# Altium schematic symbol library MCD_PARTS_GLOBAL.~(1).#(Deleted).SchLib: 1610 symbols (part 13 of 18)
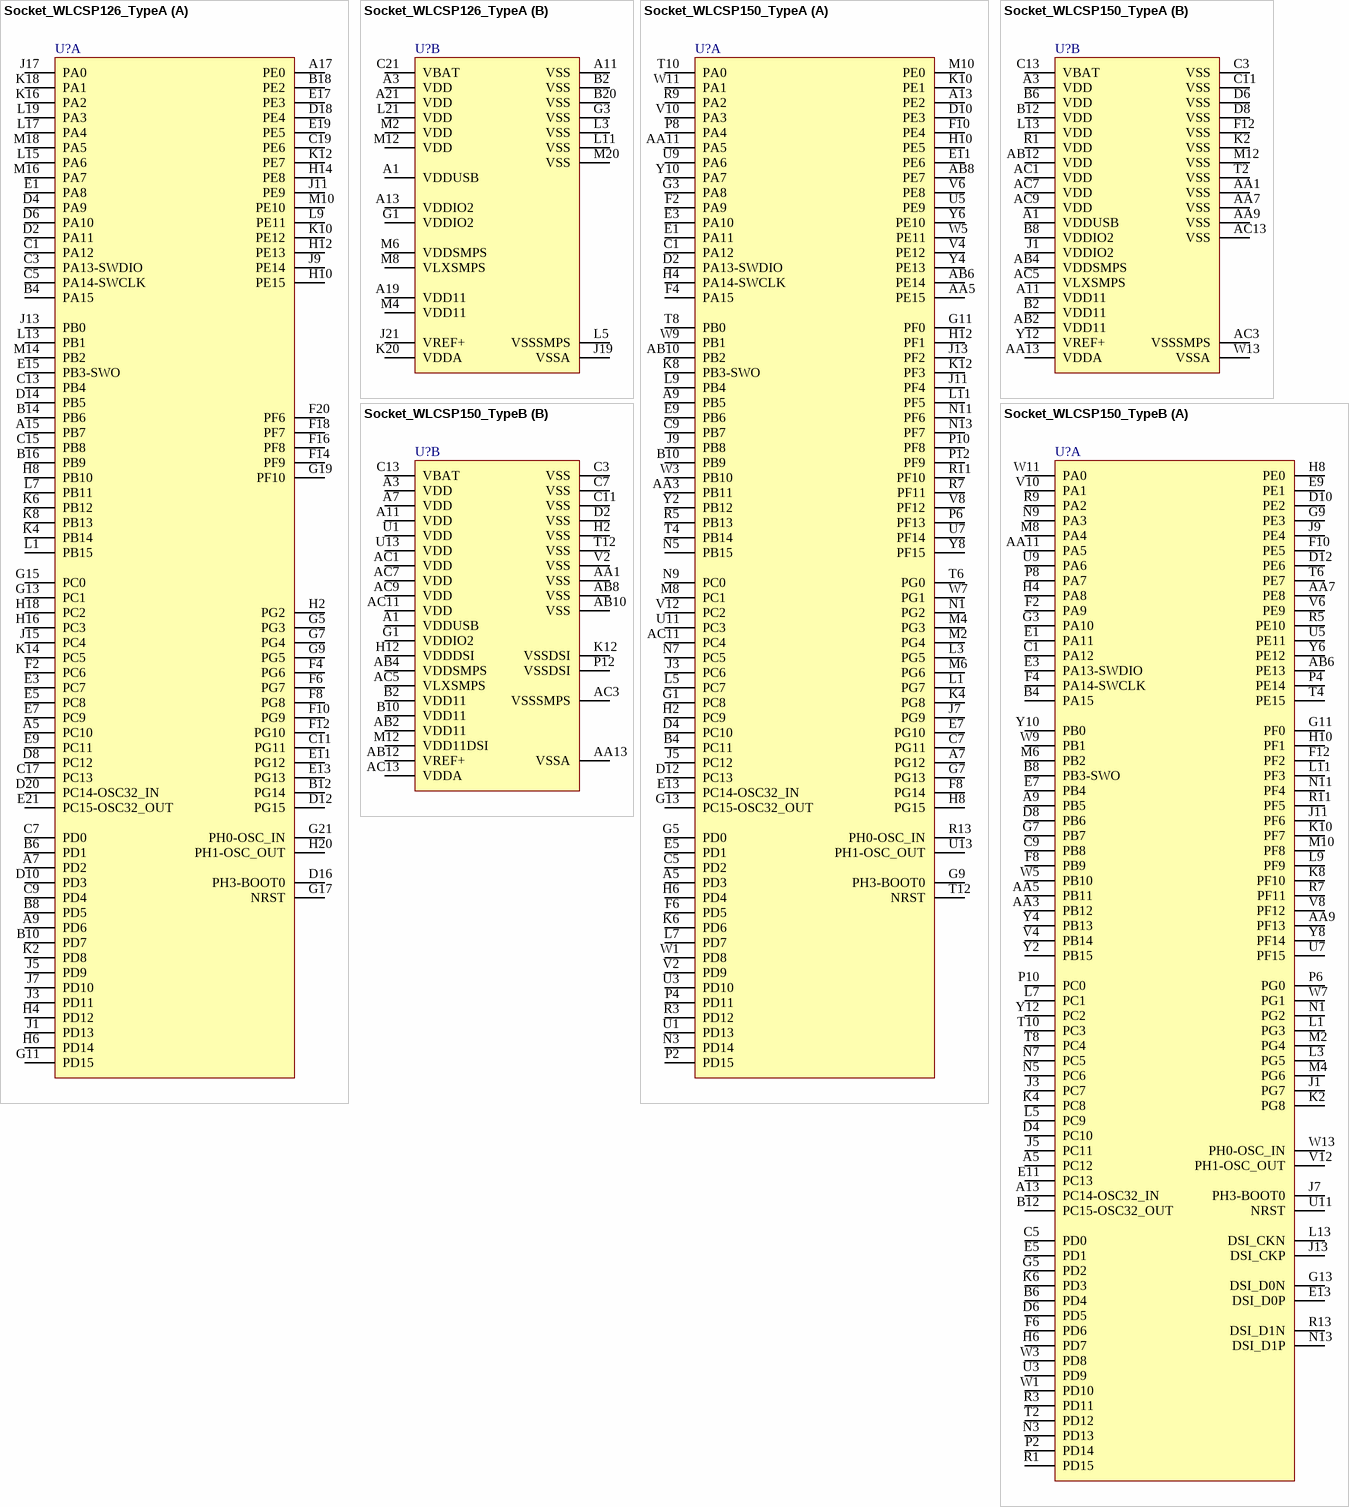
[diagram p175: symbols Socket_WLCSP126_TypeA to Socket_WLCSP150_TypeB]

## Socket_WLCSP126_TypeA
designator U?
part A pins: A5 PC10, A7 PD2, A9 PD6, A15 PB7, A17 PE0, B4 PA15, B6 PD1, B8 PD5, B10 PD7, B12 PG14, B14 PB6, B16 PB9, B18 PE2, C1 PA12, C3 PA13-SWDIO, C5 PA14-SWCLK, C7 PD0, C9 PD4, C11 PG11, C13 PB4, C15 PB8, C17 PC13, C19 PE6, D2 PA11, D4 PA9, D6 PA10, D8 PC12, D10 PD3, D12 PG15, D14 PB5, D16 PH3-BOOT0, D18 PE4, D20 PC14-OSC32_IN, E1 PA8, E3 PC7, E5 PC8, E7 PC9, E9 PC11, E11 PG12, E13 PG13, E15 PB3-SWO, E17 PE3, E19 PE5, E21 PC15-OSC32_OUT, F2 PC6, F4 PG6, F6 PG7, F8 PG8, F10 PG9, F12 PG10, F14 PF9, F16 PF8, F18 PF7, F20 PF6, G5 PG3, G7 PG4, G9 PG5, G11 PD15, G13 PC1, G15 PC0, G17 NRST, G19 PF10, G21 PH0-OSC_IN, H2 PG2, H4 PD12, H6 PD14, H8 PB10, H10 PE15, H12 PE13, H14 PE8, H16 PC3, H18 PC2, H20 PH1-OSC_OUT, J1 PD13, J3 PD11, J5 PD9, J7 PD10, J9 PE14, J11 PE9, J13 PB0, J15 PC4, J17 PA0, K2 PD8, K4 PB14, K6 PB12, K8 PB13, K10 PE12, K12 PE7, K14 PC5, K16 PA2, K18 PA1, L1 PB15, L7 PB11, L9 PE11, L13 PB1, L15 PA6, L17 PA4, L19 PA3, M10 PE10, M14 PB2, M16 PA7, M18 PA5
part B pins: A1 VDDUSB, A3 VDD, A11 VSS, A13 VDDIO2, A19 VDD11, A21 VDD, B2 VSS, B20 VSS, C21 VBAT, G1 VDDIO2, G3 VSS, J19 VSSA, J21 VREF+, K20 VDDA, L3 VSS, L5 VSSSMPS, L11 VSS, L21 VDD, M2 VDD, M4 VDD11, M6 VDDSMPS, M8 VLXSMPS, M12 VDD, M20 VSS

## Socket_WLCSP150_TypeA
designator U?
part A pins: A5 PD3, A7 PG12, A9 PB5, A13 PE2, AA3 PB11, AA5 PE15, AA11 PA5, AB6 PE14, AB8 PE7, AB10 PB2, AC11 PC4, B4 PC11, B10 PB9, C1 PA12, C5 PD2, C7 PG11, C9 PB7, D2 PA13-SWDIO, D4 PC10, D10 PE3, D12 PC13, E1 PA11, E3 PA10, E5 PD1, E7 PG10, E9 PB6, E11 PE6, E13 PC14-OSC32_IN, F2 PA9, F4 PA15, F6 PD5, F8 PG14, F10 PE4, G1 PC8, G3 PA8, G5 PD0, G7 PG13, G9 PH3-BOOT0, G11 PF0, G13 PC15-OSC32_OUT, H2 PC9, H4 PA14-SWCLK, H6 PD4, H8 PG15, H10 PE5, H12 PF1, J3 PC6, J5 PC12, J7 PG9, J9 PB8, J11 PF4, J13 PF2, K4 PG8, K6 PD6, K8 PB3-SWO, K10 PE1, K12 PF3, L1 PG7, L3 PG5, L5 PC7, L7 PD7, L9 PB4, L11 PF5, M2 PG4, M4 PG3, M6 PG6, M8 PC1, M10 PE0, N1 PG2, N3 PD14, N5 PB15, N7 PC5, N9 PC0, N11 PF6, N13 PF7, P2 PD15, P4 PD11, P6 PF13, P8 PA4, P10 PF8, P12 PF9, R3 PD12, R5 PB13, R7 PF11, R9 PA2, R11 PF10, R13 PH0-OSC_IN, T4 PB14, T6 PG0, T8 PB0, T10 PA0, T12 NRST, U1 PD13, U3 PD10, U5 PE9, U7 PF14, U9 PA6, U11 PC3, U13 PH1-OSC_OUT, V2 PD9, V4 PE12, V6 PE8, V8 PF12, V10 PA3, V12 PC2, W1 PD8, W3 PB10, W5 PE11, W7 PG1, W9 PB1, W11 PA1, Y2 PB12, Y4 PE13, Y6 PE10, Y8 PF15, Y10 PA7
part B pins: A1 VDDUSB, A3 VDD, A11 VDD11, AA1 VSS, AA7 VSS, AA9 VSS, AA13 VDDA, AB2 VDD11, AB4 VDDSMPS, AB12 VDD, AC1 VDD, AC3 VSSSMPS, AC5 VLXSMPS, AC7 VDD, AC9 VDD, AC13 VSS, B2 VDD11, B6 VDD, B8 VDDIO2, B12 VDD, C3 VSS, C11 VSS, C13 VBAT, D6 VSS, D8 VSS, F12 VSS, J1 VDDIO2, K2 VSS, L13 VDD, M12 VSS, R1 VDD, T2 VSS, W13 VSSA, Y12 VREF+

## Socket_WLCSP150_TypeB
designator U?
part A pins: A5 PC12, A9 PB5, A13 PC14-OSC32_IN, AA3 PB12, AA5 PB11, AA7 PE8, AA9 PF13, AA11 PA5, AB6 PE13, B4 PA15, B6 PD4, B8 PB3-SWO, B12 PC15-OSC32_OUT, C1 PA12, C5 PD0, C9 PB8, D4 PC10, D6 PD5, D8 PB6, D10 PE2, D12 PE6, E1 PA11, E3 PA13-SWDIO, E5 PD1, E7 PB4, E9 PE1, E11 PC13, E13 DSI_D0P, F2 PA9, F4 PA14-SWCLK, F6 PD6, F8 PB9, F10 PE5, F12 PF2, G3 PA10, G5 PD2, G7 PB7, G9 PE3, G11 PF0, G13 DSI_D0N, H4 PA8, H6 PD7, H8 PE0, H10 PF1, J1 PG7, J3 PC7, J5 PC11, J7 PH3-BOOT0, J9 PE4, J11 PF6, J13 DSI_CKP, K2 PG8, K4 PC8, K6 PD3, K8 PF10, K10 PF7, L1 PG3, L3 PG5, L5 PC9, L7 PC1, L9 PF9, L11 PF3, L13 DSI_CKN, M2 PG4, M4 PG6, M6 PB2, M8 PA4, M10 PF8, N1 PG2, N3 PD13, N5 PC6, N7 PC5, N9 PA3, N11 PF4, N13 DSI_D1P, P2 PD14, P4 PE14, P6 PG0, P8 PA7, P10 PC0, R1 PD15, R3 PD11, R5 PE10, R7 PF11, R9 PA2, R11 PF5, R13 DSI_D1N, T2 PD12, T4 PE15, T6 PE7, T8 PC4, T10 PC3, U3 PD9, U5 PE11, U7 PF15, U9 PA6, U11 NRST, V4 PB14, V6 PE9, V8 PF12, V10 PA1, V12 PH1-OSC_OUT, W1 PD10, W3 PD8, W5 PB10, W7 PG1, W9 PB1, W11 PA0, W13 PH0-OSC_IN, Y2 PB15, Y4 PB13, Y6 PE12, Y8 PF14, Y10 PB0, Y12 PC2
part B pins: A1 VDDUSB, A3 VDD, A7 VDD, A11 VDD, AA1 VSS, AA13 VSSA, AB2 VDD11, AB4 VDDSMPS, AB8 VSS, AB10 VSS, AB12 VREF+, AC1 VDD, AC3 VSSSMPS, AC5 VLXSMPS, AC7 VDD, AC9 VDD, AC11 VDD, AC13 VDDA, B2 VDD11, B10 VDD11, C3 VSS, C7 VSS, C11 VSS, C13 VBAT, D2 VSS, G1 VDDIO2, H2 VSS, H12 VDDDSI, K12 VSSDSI, M12 VDD11DSI, P12 VSSDSI, T12 VSS, U1 VDD, U13 VDD, V2 VSS

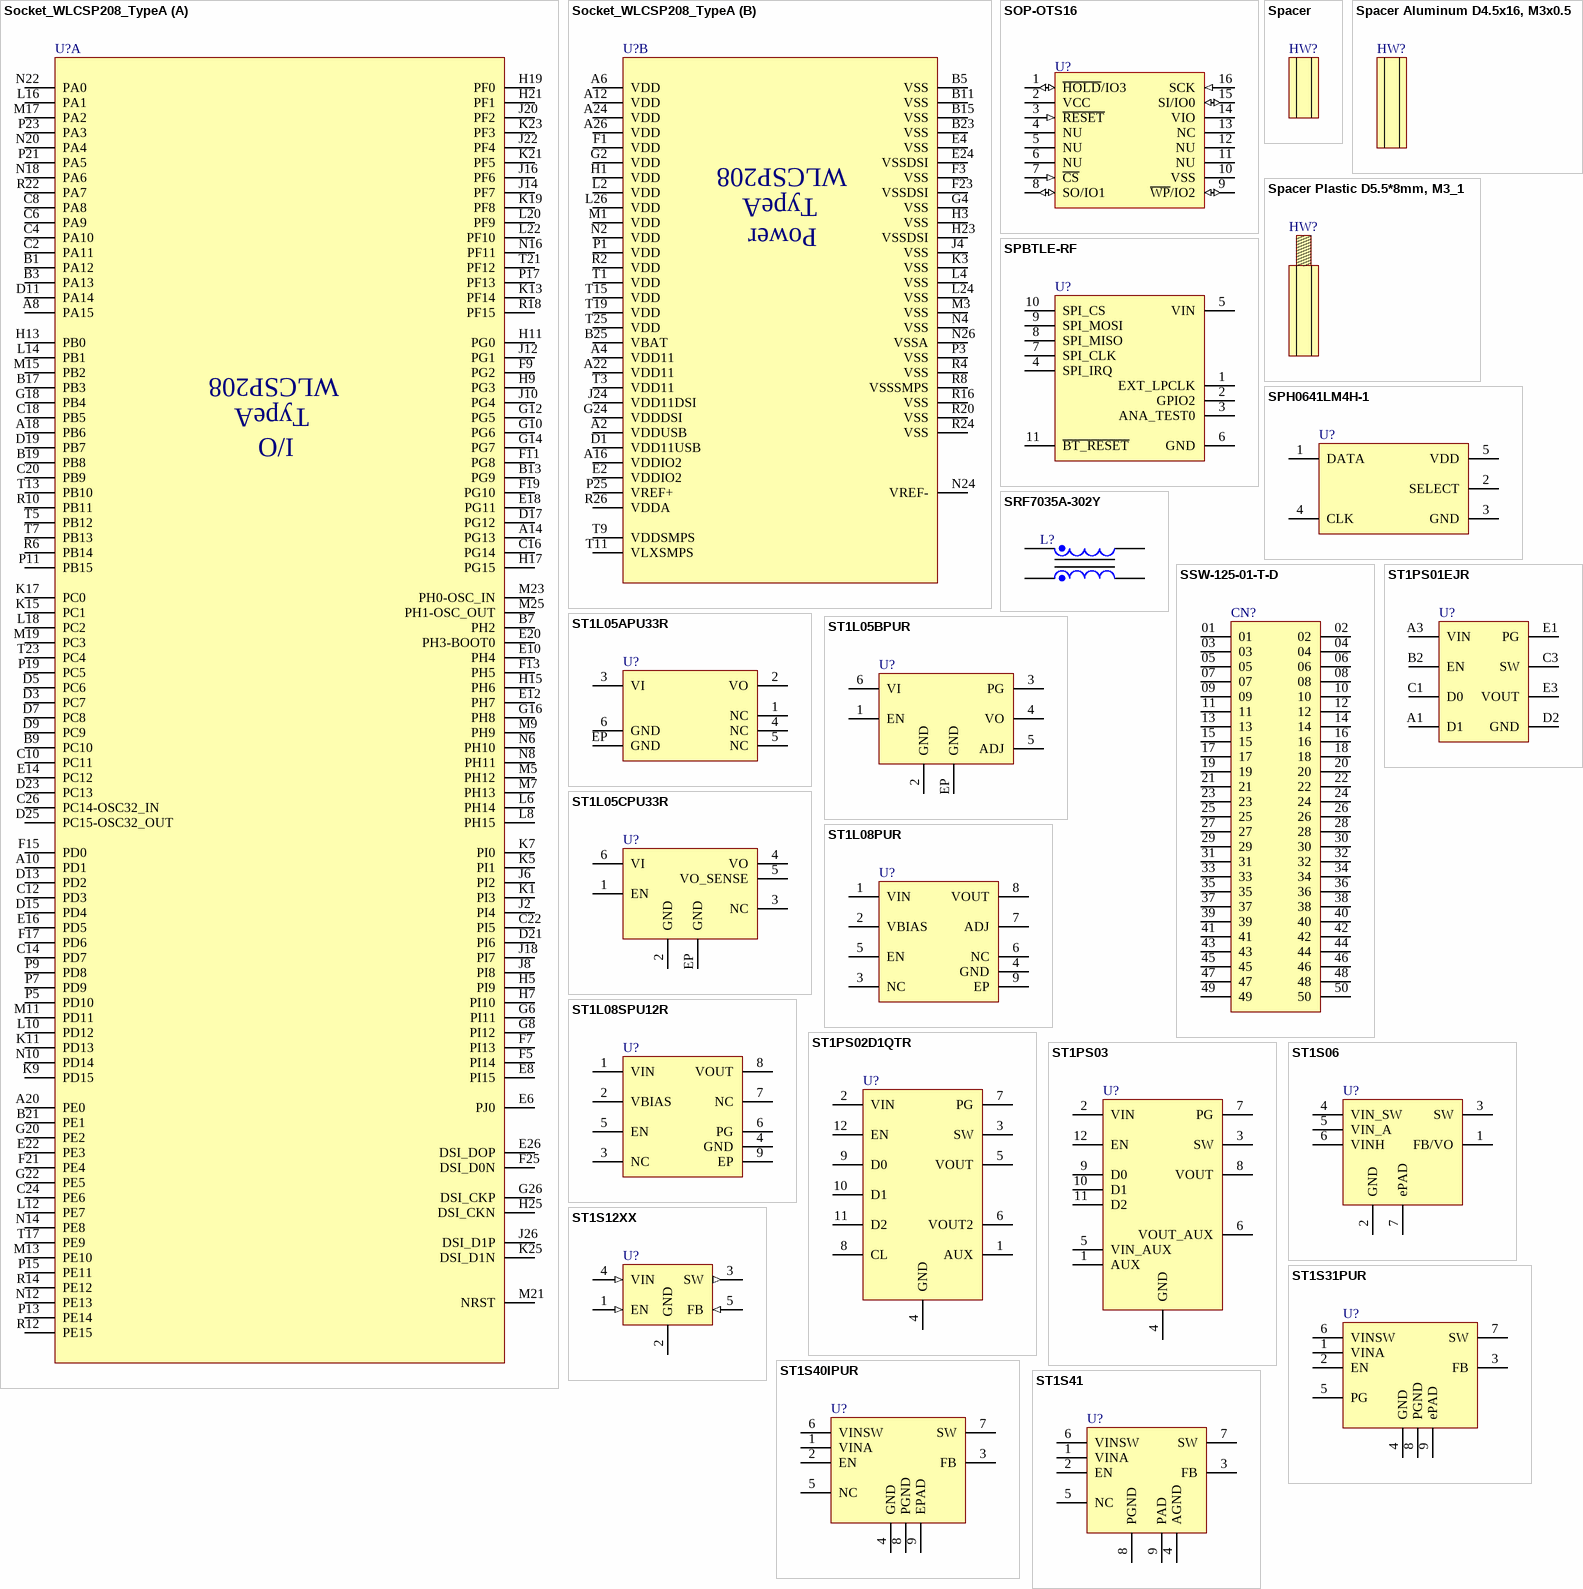
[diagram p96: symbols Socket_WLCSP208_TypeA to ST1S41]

## Socket_WLCSP208_TypeA
designator U?
part A pins: A8 PA15, A10 PD1, A14 PG13, A18 PB6, A20 PE0, B1 PA12, B3 PA13, B7 PH2, B9 PC10, B13 PG9, B17 PB3, B19 PB8, B21 PE1, C2 PA11, C4 PA10, C6 PA9, C8 PA8, C10 PC11, C12 PD3, C14 PD7, C16 PG14, C18 PB5, C20 PB9, C22 PI5, C24 PE6, C26 PC14-OSC32_IN, D3 PC7, D5 PC6, D7 PC8, D9 PC9, D11 PA14, D13 PD2, D15 PD4, D17 PG12, D19 PB7, D21 PI6, D23 PC13, D25 PC15-OSC32_OUT, E6 PJ0, E8 PI15, E10 PH4, E12 PH7, E14 PC12, E16 PD5, E18 PG11, E20 PH3-BOOT0, E22 PE3, E26 DSI_DOP, F5 PI14, F7 PI13, F9 PG2, F11 PG8, F13 PH5, F15 PD0, F17 PD6, F19 PG10, F21 PE4, F25 DSI_D0N, G6 PI11, G8 PI12, G10 PG6, G12 PG5, G14 PG7, G16 PH8, G18 PB4, G20 PE2, G22 PE5, G26 DSI_CKP, H5 PI9, H7 PI10, H9 PG3, H11 PG0, H13 PB0, H15 PH6, H17 PG15, H19 PF0, H21 PF1, H25 DSI_CKN, J2 PI4, J6 PI2, J8 PI8, J10 PG4, J12 PG1, J14 PF7, J16 PF6, J18 PI7, J20 PF2, J22 PF4, J26 DSI_D1P, K1 PI3, K5 PI1, K7 PI0, K9 PD15, K11 PD13, K13 PF14, K15 PC1, K17 PC0, K19 PF8, K21 PF5, K23 PF3, K25 DSI_D1N, L6 PH14, L8 PH15, L10 PD12, L12 PE7, L14 PB1, L16 PA1, L18 PC2, L20 PF9, L22 PF10, M5 PH12, M7 PH13, M9 PH9, M11 PD11, M13 PE10, M15 PB2, M17 PA2, M19 PC3, M21 NRST, M23 PH0-OSC_IN, M25 PH1-OSC_OUT, N6 PH10, N8 PH11, N10 PD14, N12 PE13, N14 PE8, N16 PF11, N18 PA6, N20 PA4, N22 PA0, P5 PD10, P7 PD9, P9 PD8, P11 PB15, P13 PE14, P15 PE11, P17 PF13, P19 PC5, P21 PA5, P23 PA3, R6 PB14, R10 PB11, R12 PE15, R14 PE12, R18 PF15, R22 PA7, T5 PB12, T7 PB13, T13 PB10, T17 PE9, T21 PF12, T23 PC4
part B pins: A2 VDDUSB, A4 VDD11, A6 VDD, A12 VDD, A16 VDDIO2, A22 VDD11, A24 VDD, A26 VDD, B5 VSS, B11 VSS, B15 VSS, B23 VSS, B25 VBAT, D1 VDD11USB, E2 VDDIO2, E4 VSS, E24 VSSDSI, F1 VDD, F3 VSS, F23 VSSDSI, G2 VDD, G4 VSS, G24 VDDDSI, H1 VDD, H3 VSS, H23 VSSDSI, J4 VSS, J24 VDD11DSI, K3 VSS, L2 VDD, L4 VSS, L24 VSS, L26 VDD, M1 VDD, M3 VSS, N2 VDD, N4 VSS, N24 VREF-, N26 VSSA, P1 VDD, P3 VSS, P25 VREF+, R2 VDD, R4 VSS, R8 VSSSMPS, R16 VSS, R20 VSS, R24 VSS, R26 VDDA, T1 VDD, T3 VDD11, T9 VDDSMPS, T11 VLXSMPS, T15 VDD, T19 VDD, T25 VDD

## SOP-OTS16
designator U?
pins: 1 ~{HOLD}/IO3 (io), 2 VCC (power), 3 ~{RESET} (in), 4 NU, 5 NU, 6 NU, 7 ~{CS} (in), 8 SO/IO1 (io), 9 ~{WP}/IO2 (io), 10 VSS (power), 11 NU, 12 NU, 13 NC, 14 VIO, 15 SI/IO0 (io), 16 SCK (in)

## Spacer
designator HW?  (mechanical)

## Spacer Aluminum D4.5x16, M3x0.5
designator HW?  (mechanical)

## Spacer Plastic D5.5*8mm, M3_1
designator HW?  (mechanical)

## SPBTLE-RF
designator U?
pins: 1 EXT_LPCLK, 2 GPIO2, 3 ANA_TEST0, 4 SPI_IRQ, 5 VIN, 6 GND, 7 SPI_CLK, 8 SPI_MISO, 9 SPI_MOSI, 10 SPI_CS, 11 ~{BT}~{_RESET}

## SPH0641LM4H-1
designator U?
pins: 1 DATA, 2 SELECT, 3 GND, 4 CLK, 5 VDD

## SRF7035A-302Y
designator L?
pins: 1, 2, 3, 4

## SSW-125-01-T-D
designator CN?
pins: 01, 02, 03, 04, 05, 06, 07, 08, 09, 10, 11, 12, 13, 14, 15, 16, 17, 18, 19, 20, 21, 22, 23, 24, 25, 26, 27, 28, 29, 30, 31, 32, 33, 34, 35, 36, 37, 38, 39, 40, 41, 42, 43, 44, 45, 46, 47, 48, 49, 50

## ST1L05APU33R
designator U?
pins: 1 NC, 2 VO, 3 VI, 4 NC, 5 NC, 6 GND, EP GND

## ST1L05BPUR
designator U?
pins: 1 EN, 2 GND, 3 PG, 4 VO, 5 ADJ, 6 VI, EP GND

## ST1L05CPU33R
designator U?
pins: 1 EN, 2 GND, 3 NC, 4 VO, 5 VO_SENSE, 6 VI, EP GND

## ST1L08PUR
designator U?
pins: 1 VIN, 2 VBIAS, 3 NC, 4 GND, 5 EN, 6 NC, 7 ADJ, 8 VOUT, 9 EP

## ST1L08SPU12R
designator U?
pins: 1 VIN, 2 VBIAS, 3 NC, 4 GND, 5 EN, 6 PG, 7 NC, 8 VOUT, 9 EP

## ST1PS01EJR
designator U?
pins: A1 D1, A3 VIN, B2 EN, C1 D0, C3 SW, D2 GND, E1 PG, E3 VOUT

## ST1PS02D1QTR
designator U?
pins: 1 AUX, 2 VIN, 3 SW, 4 GND, 5 VOUT, 6 VOUT2, 7 PG, 8 CL, 9 D0, 10 D1, 11 D2, 12 EN

## ST1PS03
designator U?
pins: 1 AUX, 2 VIN, 3 SW, 4 GND, 5 VIN_AUX, 6 VOUT_AUX, 7 PG, 8 VOUT, 9 D0, 10 D1, 11 D2, 12 EN

## ST1S06
designator U?
pins: 1 FB/VO, 2 GND, 3 SW, 4 VIN_SW, 5 VIN_A, 6 VINH, 7 ePAD

## ST1S12XX
designator U?
pins: 1 EN (in), 2 GND, 3 SW (out), 4 VIN (in), 5 FB (in)

## ST1S31PUR
designator U?
pins: 1 VINA, 2 EN, 3 FB, 4 GND, 5 PG, 6 VINSW, 7 SW, 8 PGND, 9 ePAD

## ST1S40IPUR
designator U?
pins: 1 VINA, 2 EN, 3 FB, 4 GND, 5 NC, 6 VINSW, 7 SW, 8 PGND, 9 EPAD

## ST1S41
designator U?
pins: 1 VINA, 2 EN, 3 FB, 4 AGND, 5 NC, 6 VINSW, 7 SW, 8 PGND, 9 PAD

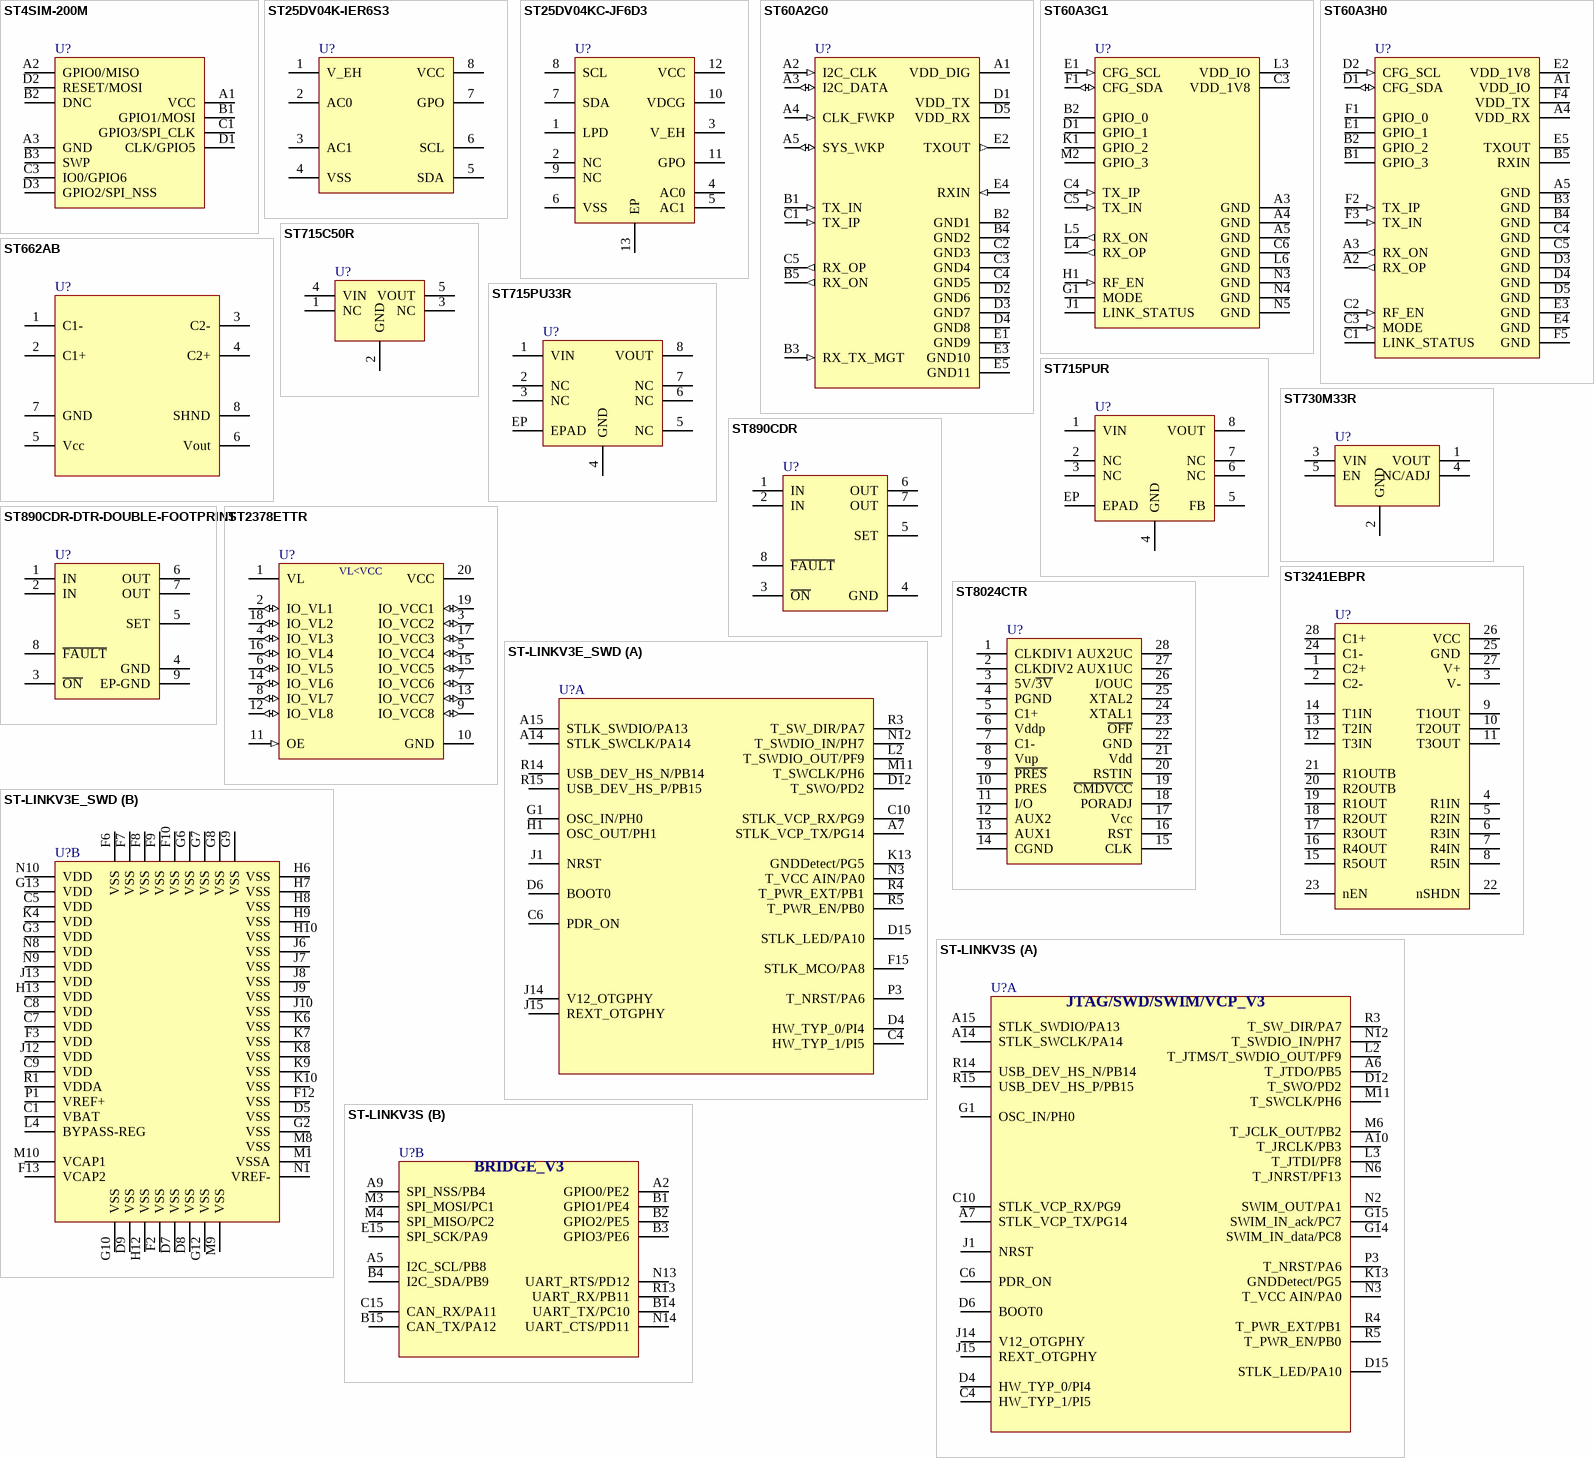
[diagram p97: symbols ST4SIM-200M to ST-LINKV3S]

## ST4SIM-200M
designator U?
pins: A1 VCC, A2 GPIO0/MISO, A3 GND, B1 GPIO1/MOSI, B2 DNC, B3 SWP, C1 GPIO3/SPI_CLK, C3 IO0/GPIO6, D1 CLK/GPIO5, D2 RESET/MOSI, D3 GPIO2/SPI_NSS

## ST25DV04K-IER6S3
designator U?
pins: 1 V_EH, 2 AC0, 3 AC1, 4 VSS, 5 SDA, 6 SCL, 7 GPO, 8 VCC

## ST25DV04KC-JF6D3
designator U?
pins: 1 LPD, 2 NC, 3 V_EH, 4 AC0, 5 AC1, 6 VSS, 7 SDA, 8 SCL, 9 NC, 10 VDCG, 11 GPO, 12 VCC, 13 EP

## ST60A2G0
designator U?
pins: A1 VDD_DIG (power), A2 I2C_CLK (in), A3 I2C_DATA (io), A4 CLK_FWKP (in), A5 SYS_WKP (io), B1 TX_IN (in), B2 GND1, B3 RX_TX_MGT (in), B4 GND2, B5 RX_ON (out), C1 TX_IP (in), C2 GND3, C3 GND4, C4 GND5, C5 RX_OP (out), D1 VDD_TX (power), D2 GND6, D3 GND7, D4 GND8, D5 VDD_RX (power), E1 GND9, E2 TXOUT (out), E3 GND10, E4 RXIN (in), E5 GND11

## ST60A3G1
designator U?
pins: A3 GND, A4 GND, A5 GND, B2 GPIO_0, C3 VDD_1V8 (power), C4 TX_IP (in), C5 TX_IN (in), C6 GND, D1 GPIO_1, E1 CFG_SCL (in), F1 CFG_SDA (io), G1 MODE, H1 RF_EN (in), J1 LINK_STATUS, K1 GPIO_2, L3 VDD_IO (power), L4 RX_OP (out), L5 RX_ON (out), L6 GND, M2 GPIO_3, N3 GND, N4 GND, N5 GND

## ST60A3H0
designator U?
pins: A1 VDD_IO (power), A2 RX_OP (out), A3 RX_ON (out), A4 VDD_RX (power), A5 GND, B1 GPIO_3, B2 GPIO_2, B3 GND, B4 GND, B5 RXIN (power), C1 LINK_STATUS, C2 RF_EN (in), C3 MODE (in), C4 GND, C5 GND, D1 CFG_SDA (io), D2 CFG_SCL (in), D3 GND, D4 GND, D5 GND, E1 GPIO_1, E2 VDD_1V8 (power), E3 GND, E4 GND, E5 TXOUT (power), F1 GPIO_0, F2 TX_IP (in), F3 TX_IN (in), F4 VDD_TX (power), F5 GND

## ST662AB
designator U?
pins: 1 C1-, 2 C1+, 3 C2-, 4 C2+, 5 Vcc, 6 Vout, 7 GND, 8 SHND

## ST715C50R
designator U?
pins: 1 NC, 2 GND, 3 NC, 4 VIN, 5 VOUT

## ST715PU33R
designator U?
pins: 1 VIN, 2 NC, 3 NC, 4 GND, 5 NC, 6 NC, 7 NC, 8 VOUT, EP EPAD

## ST715PUR
designator U?
pins: 1 VIN, 2 NC, 3 NC, 4 GND, 5 FB, 6 NC, 7 NC, 8 VOUT, EP EPAD

## ST730M33R
designator U?
pins: 1 VOUT, 2 GND, 3 VIN, 4 NC/ADJ, 5 EN

## ST890CDR
designator U?
pins: 1 IN, 2 IN, 3 ~{ON}, 4 GND, 5 SET, 6 OUT, 7 OUT, 8 ~{FAULT}

## ST890CDR-DTR-DOUBLE-FOOTPRINT
designator U?
pins: 1 IN, 2 IN, 3 ~{ON}, 4 GND, 5 SET, 6 OUT, 7 OUT, 8 ~{FAULT}, 9 EP-GND

## ST2378ETTR
designator U?
pins: 1 VL (power), 2 IO_VL1 (io), 3 IO_VCC2 (io), 4 IO_VL3 (io), 5 IO_VCC4 (io), 6 IO_VL5 (io), 7 IO_VCC6 (io), 8 IO_VL7 (io), 9 IO_VCC8 (io), 10 GND, 11 OE (in), 12 IO_VL8 (io), 13 IO_VCC7 (io), 14 IO_VL6 (io), 15 IO_VCC5 (io), 16 IO_VL4 (io), 17 IO_VCC3 (io), 18 IO_VL2 (io), 19 IO_VCC1 (io), 20 VCC (power)

## ST3241EBPR
designator U?
pins: 1 C2+, 2 C2-, 3 V-, 4 R1IN, 5 R2IN, 6 R3IN, 7 R4IN, 8 R5IN, 9 T1OUT, 10 T2OUT, 11 T3OUT, 12 T3IN, 13 T2IN, 14 T1IN, 15 R5OUT, 16 R4OUT, 17 R3OUT, 18 R2OUT, 19 R1OUT, 20 R2OUTB, 21 R1OUTB, 22 nSHDN, 23 nEN, 24 C1-, 25 GND, 26 VCC, 27 V+, 28 C1+

## ST8024CTR
designator U?
pins: 1 CLKDIV1, 2 CLKDIV2, 3 5V/~{3V}, 4 PGND, 5 C1+, 6 Vddp, 7 C1-, 8 Vup, 9 ~{PRES}, 10 PRES, 11 I/O, 12 AUX2, 13 AUX1, 14 CGND, 15 CLK, 16 RST, 17 Vcc, 18 PORADJ, 19 ~{CMDVCC}, 20 RSTIN, 21 Vdd, 22 GND, 23 ~{OFF}, 24 XTAL1, 25 XTAL2, 26 I/OUC, 27 AUX1UC, 28 AUX2UC

## ST-LINKV3E_SWD
designator U?
part A pins: A7 STLK_VCP_TX/PG14, A14 STLK_SWCLK/PA14, A15 STLK_SWDIO/PA13, C4 HW_TYP_1/PI5, C6 PDR_ON, C10 STLK_VCP_RX/PG9, D4 HW_TYP_0/PI4, D6 BOOT0, D12 T_SWO/PD2, D15 STLK_LED/PA10, F15 STLK_MCO/PA8, G1 OSC_IN/PH0, H1 OSC_OUT/PH1, J1 NRST, J14 V12_OTGPHY, J15 REXT_OTGPHY, K13 GNDDetect/PG5, L2 T_SWDIO_OUT/PF9, M11 T_SWCLK/PH6, N3 T_VCC AIN/PA0, N12 T_SWDIO_IN/PH7, P3 T_NRST/PA6, R3 T_SW_DIR/PA7, R4 T_PWR_EXT/PB1, R5 T_PWR_EN/PB0, R14 USB_DEV_HS_N/PB14, R15 USB_DEV_HS_P/PB15
part B pins: C1 VBAT, C5 VDD, C7 VDD, C8 VDD, C9 VDD, D5 VSS, D7 VSS, D8 VSS, D9 VSS, F2 VSS, F3 VDD, F6 VSS, F7 VSS, F8 VSS, F9 VSS, F10 VSS, F12 VSS, F13 VCAP2, G2 VSS, G3 VDD, G6 VSS, G7 VSS, G8 VSS, G9 VSS, G10 VSS, G12 VSS, G13 VDD, H6 VSS, H7 VSS, H8 VSS, H9 VSS, H10 VSS, H12 VSS, H13 VDD, J6 VSS, J7 VSS, J8 VSS, J9 VSS, J10 VSS, J12 VDD, J13 VDD, K4 VDD, K6 VSS, K7 VSS, K8 VSS, K9 VSS, K10 VSS, L4 BYPASS-REG, M1 VSSA, M8 VSS, M9 VSS, M10 VCAP1, N1 VREF-, N8 VDD, N9 VDD, N10 VDD, P1 VREF+, R1 VDDA

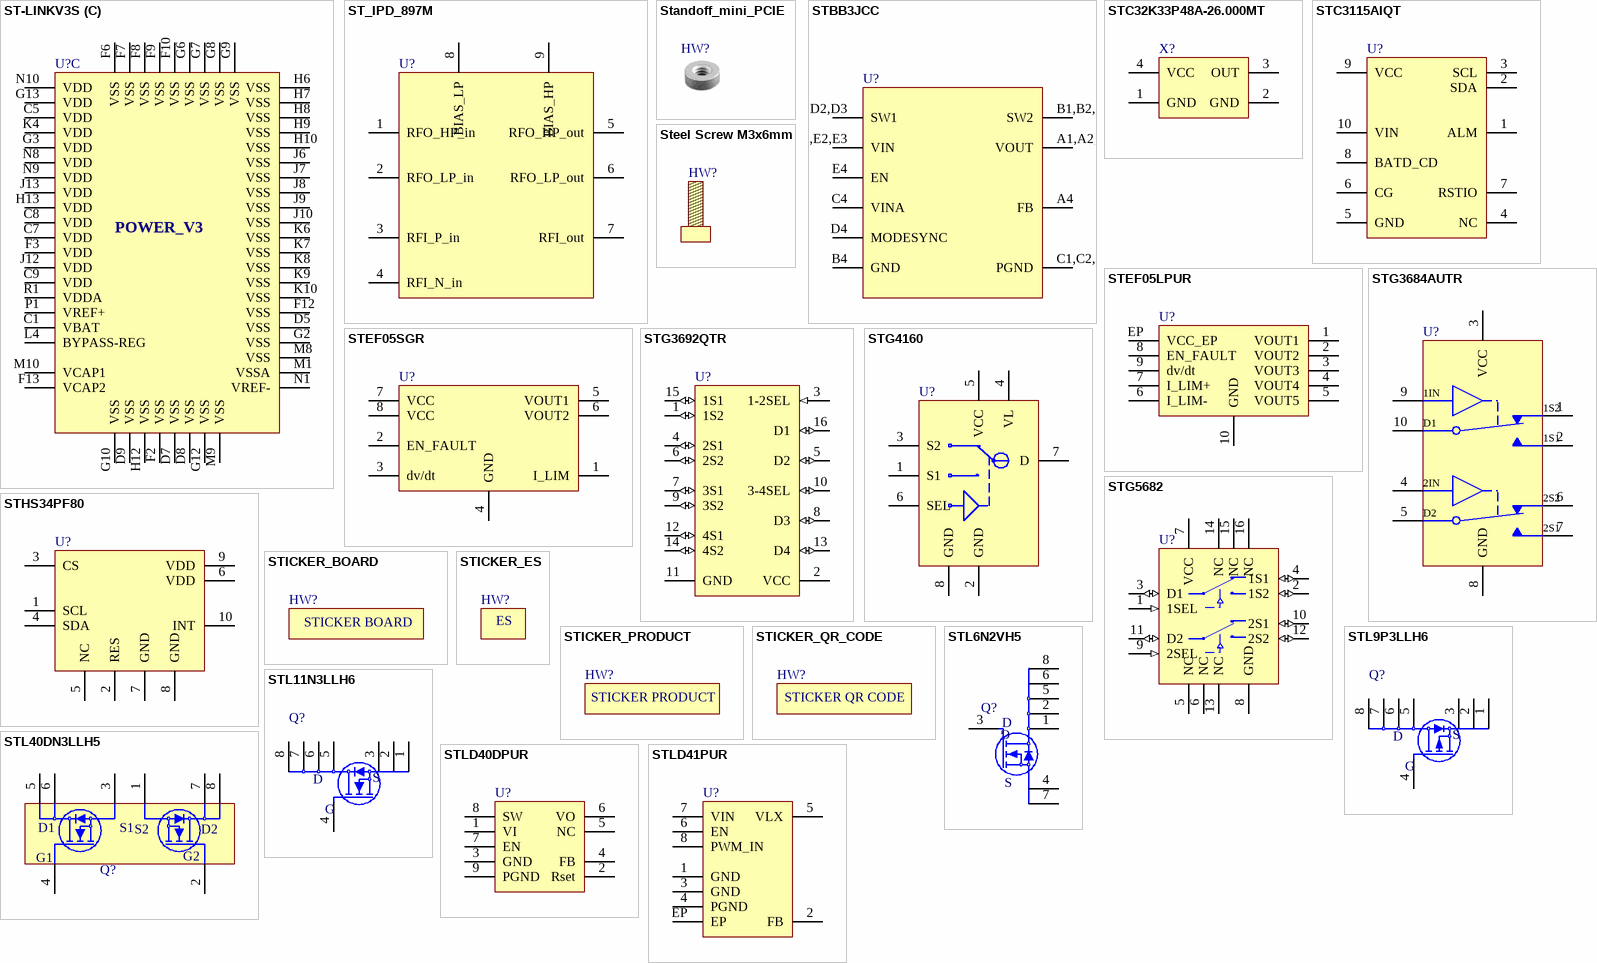
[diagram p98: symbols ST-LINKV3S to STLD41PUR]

## ST-LINKV3S
designator U?
part A pins: A6 T_JTDO/PB5, A7 STLK_VCP_TX/PG14, A10 T_JRCLK/PB3, A14 STLK_SWCLK/PA14, A15 STLK_SWDIO/PA13, C4 HW_TYP_1/PI5, C6 PDR_ON, C10 STLK_VCP_RX/PG9, D4 HW_TYP_0/PI4, D6 BOOT0, D12 T_SWO/PD2, D15 STLK_LED/PA10, G1 OSC_IN/PH0, G14 SWIM_IN_data/PC8, G15 SWIM_IN_ack/PC7, J1 NRST, J14 V12_OTGPHY, J15 REXT_OTGPHY, K13 GNDDetect/PG5, L2 T_JTMS/T_SWDIO_OUT/PF9, L3 T_JTDI/PF8, M6 T_JCLK_OUT/PB2, M11 T_SWCLK/PH6, N2 SWIM_OUT/PA1, N3 T_VCC AIN/PA0, N6 T_JNRST/PF13, N12 T_SWDIO_IN/PH7, P3 T_NRST/PA6, R3 T_SW_DIR/PA7, R4 T_PWR_EXT/PB1, R5 T_PWR_EN/PB0, R14 USB_DEV_HS_N/PB14, R15 USB_DEV_HS_P/PB15
part B pins: A2 GPIO0/PE2, A5 I2C_SCL/PB8, A9 SPI_NSS/PB4, B1 GPIO1/PE4, B2 GPIO2/PE5, B3 GPIO3/PE6, B4 I2C_SDA/PB9, B14 UART_TX/PC10, B15 CAN_TX/PA12, C15 CAN_RX/PA11, E15 SPI_SCK/PA9, M3 SPI_MOSI/PC1, M4 SPI_MISO/PC2, N13 UART_RTS/PD12, N14 UART_CTS/PD11, R13 UART_RX/PB11
part C pins: C1 VBAT, C5 VDD, C7 VDD, C8 VDD, C9 VDD, D5 VSS, D7 VSS, D8 VSS, D9 VSS, F2 VSS, F3 VDD, F6 VSS, F7 VSS, F8 VSS, F9 VSS, F10 VSS, F12 VSS, F13 VCAP2, G2 VSS, G3 VDD, G6 VSS, G7 VSS, G8 VSS, G9 VSS, G10 VSS, G12 VSS, G13 VDD, H6 VSS, H7 VSS, H8 VSS, H9 VSS, H10 VSS, H12 VSS, H13 VDD, J6 VSS, J7 VSS, J8 VSS, J9 VSS, J10 VSS, J12 VDD, J13 VDD, K4 VDD, K6 VSS, K7 VSS, K8 VSS, K9 VSS, K10 VSS, L4 BYPASS-REG, M1 VSSA, M8 VSS, M9 VSS, M10 VCAP1, N1 VREF-, N8 VDD, N9 VDD, N10 VDD, P1 VREF+, R1 VDDA

## ST_IPD_897M
designator U?
pins: 1 RFO_HP_in, 2 RFO_LP_in, 3 RFI_P_in, 4 RFI_N_in, 5 RFO_HP_out, 6 RFO_LP_out, 7 RFI_out, 8 BIAS_LP, 9 BIAS_HP

## Standoff_mini_PCIE
designator HW?  (mechanical)

## STBB3JCC
designator U?
pins: A1,A2,A3 VOUT, A4 FB, B1,B2,B3 SW2, B4 GND, C1,C2,C3 PGND, C4 VINA, D1,D2,D3 SW1, D4 MODESYNC, E1,E2,E3 VIN, E4 EN

## STC32K33P48A-26.000MT
designator X?
footprint STC32K
pins: 1 GND, 2 GND, 3 OUT, 4 VCC

## STC3115AIQT
designator U?
pins: 1 ALM, 2 SDA, 3 SCL, 4 NC, 5 GND, 6 CG, 7 RSTIO, 8 BATD_CD, 9 VCC, 10 VIN

## Steel Screw M3x6mm
designator HW?  (mechanical)

## STEF05LPUR
designator U?
pins: 1 VOUT1, 2 VOUT2, 3 VOUT3, 4 VOUT4, 5 VOUT5, 6 I_LIM-, 7 I_LIM+, 8 EN_FAULT, 9 dv/dt, 10 GND, EP VCC_EP

## STEF05SGR
designator U?
pins: 1 I_LIM, 2 EN_FAULT, 3 dv/dt, 4 GND, 5 VOUT1, 6 VOUT2, 7 VCC, 8 VCC

## STG3684AUTR
designator U?
pins: 1 1S2, 2 1S1, 3 VCC, 4 2IN, 5 D2, 6 2S2, 7 2S1, 8 GND, 9 1IN, 10 D1

## STG3692QTR
designator U?
pins: 1 1S2 (io), 2 VCC (power), 3 1-2SEL (in), 4 2S1 (io), 5 D2 (io), 6 2S2 (io), 7 3S1 (io), 8 D3 (io), 9 3S2 (io), 10 3-4SEL (io), 11 GND (power), 12 4S1 (io), 13 D4 (io), 14 4S2 (io), 15 1S1 (io), 16 D1 (io)

## STG4160
designator U?
pins: 1 S1, 2 GND (power), 3 S2, 4 VL, 5 VCC, 6 SEL, 7 D, 8 GND (power)

## STG5682
designator U?
pins: 1 1SEL (in), 2 1S2 (io), 3 D1 (io), 4 1S1 (io), 5 NC, 6 NC, 7 VCC (power), 8 GND, 9 2SEL (in), 10 2S1 (io), 11 D2 (io), 12 2S2 (io), 13 NC, 14 NC, 15 NC, 16 NC

## STHS34PF80
designator U?
pins: 1 SCL, 2 RES, 3 CS, 4 SDA, 5 NC, 6 VDD, 7 GND, 8 GND, 9 VDD, 10 INT

## STICKER_BOARD
designator HW?  (no BOM)

## STICKER_ES
designator HW?  (no BOM)

## STICKER_PRODUCT
designator HW?  (no BOM)

## STICKER_QR_CODE
designator HW?  (no BOM)

## STL6N2VH5
designator Q?
pins: 1 D, 2 D, 3 G, 4 S, 5 D, 6 D, 7 S, 8 D

## STL9P3LLH6
designator Q?
pins: 1 S, 2 S, 3 S, 4 G, 5 D, 6 D, 7 D, 8 D

## STL11N3LLH6
designator Q?
pins: 1 S, 2 S, 3 S, 4 G, 5 D, 6 D, 7 D, 8 D

## STL40DN3LLH5
designator Q?
pins: 1 S2, 2 G2, 3 S1, 4 G1, 5 D1, 6 D1, 7 D2, 8 D2

## STLD40DPUR
designator U?
pins: 1 VI, 2 Rset, 3 GND, 4 FB, 5 NC, 6 VO, 7 EN, 8 SW, 9 PGND

## STLD41PUR
designator U?
pins: 1 GND, 2 FB, 3 GND, 4 PGND, 5 VLX, 6 EN, 7 VIN, 8 PWM_IN, EP

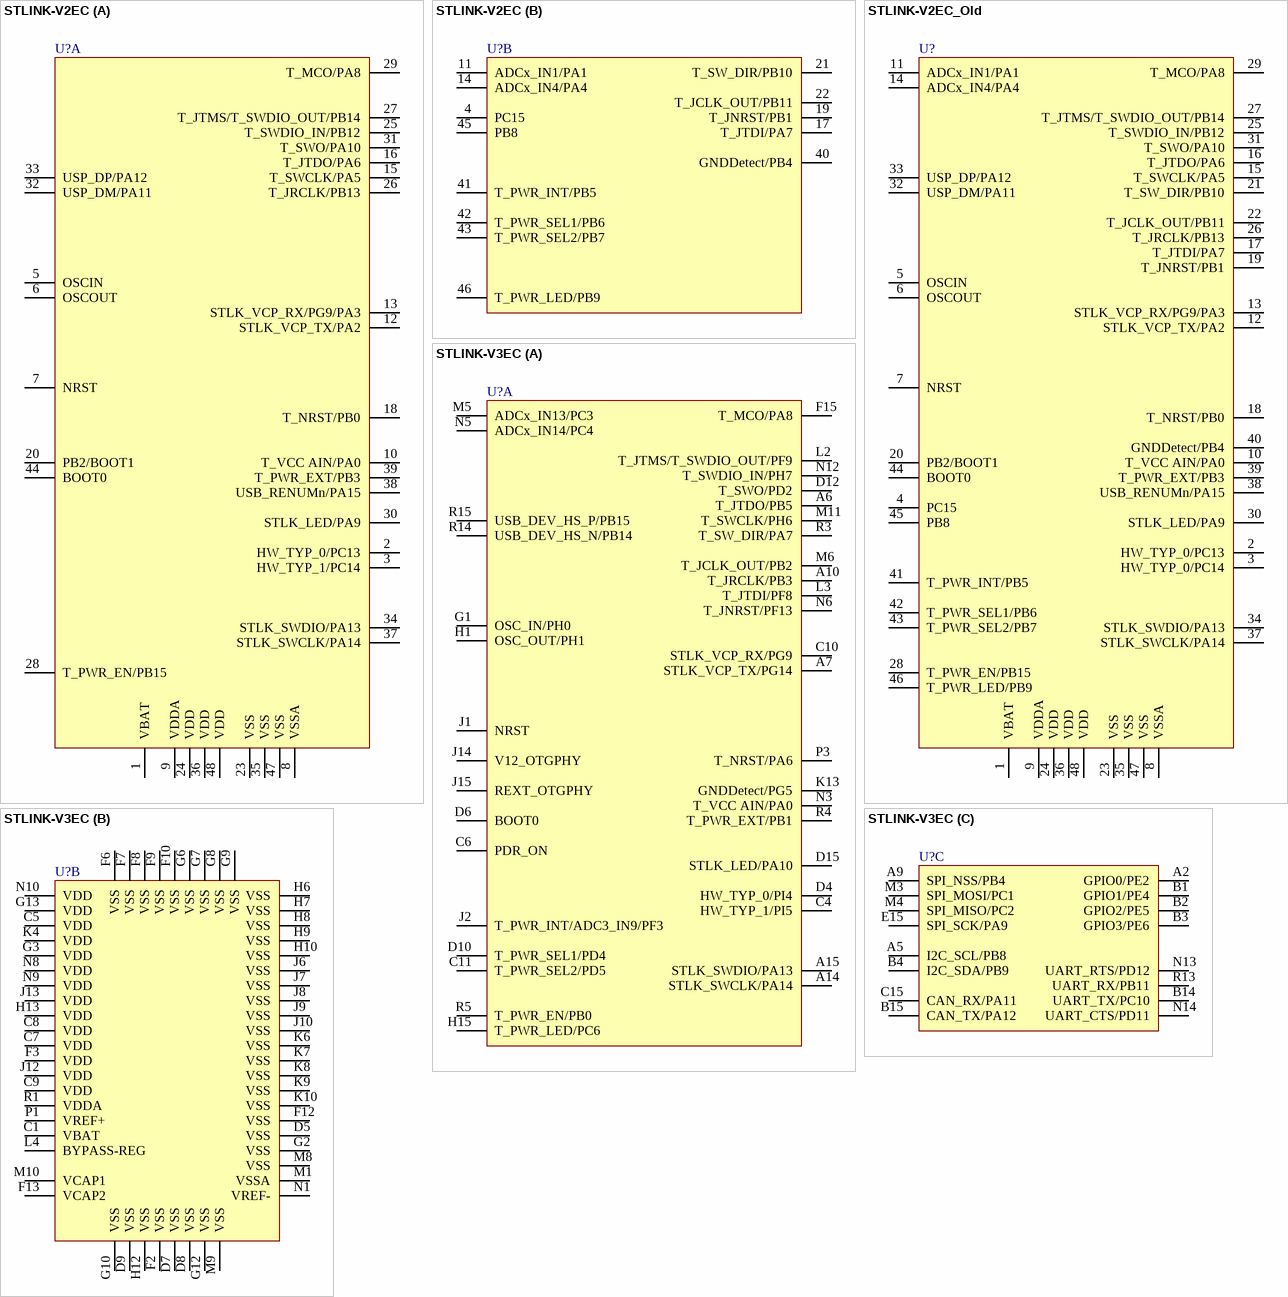
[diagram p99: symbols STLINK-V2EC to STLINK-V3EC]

## STLINK-V2EC
designator U?
part A pins: 1 VBAT, 2 HW_TYP_0/PC13, 3 HW_TYP_1/PC14, 5 OSCIN, 6 OSCOUT, 7 NRST, 8 VSSA, 9 VDDA, 10 T_VCC AIN/PA0, 12 STLK_VCP_TX/PA2, 13 STLK_VCP_RX/PG9/PA3, 15 T_SWCLK/PA5, 16 T_JTDO/PA6, 18 T_NRST/PB0, 20 PB2/BOOT1, 23 VSS, 24 VDD, 25 T_SWDIO_IN/PB12, 26 T_JRCLK/PB13, 27 T_JTMS/T_SWDIO_OUT/PB14, 28 T_PWR_EN/PB15, 29 T_MCO/PA8, 30 STLK_LED/PA9, 31 T_SWO/PA10, 32 USP_DM/PA11, 33 USP_DP/PA12, 34 STLK_SWDIO/PA13, 35 VSS, 36 VDD, 37 STLK_SWCLK/PA14, 38 USB_RENUMn/PA15, 39 T_PWR_EXT/PB3, 44 BOOT0, 47 VSS, 48 VDD
part B pins: 4 PC15, 11 ADCx_IN1/PA1, 14 ADCx_IN4/PA4, 17 T_JTDI/PA7, 19 T_JNRST/PB1, 21 T_SW_DIR/PB10, 22 T_JCLK_OUT/PB11, 40 GNDDetect/PB4, 41 T_PWR_INT/PB5, 42 T_PWR_SEL1/PB6, 43 T_PWR_SEL2/PB7, 45 PB8, 46 T_PWR_LED/PB9

## STLINK-V2EC_Old
designator U?
pins: 1 VBAT, 2 HW_TYP_0/PC13, 3 HW_TYP_0/PC14, 4 PC15, 5 OSCIN, 6 OSCOUT, 7 NRST, 8 VSSA, 9 VDDA, 10 T_VCC AIN/PA0, 11 ADCx_IN1/PA1, 12 STLK_VCP_TX/PA2, 13 STLK_VCP_RX/PG9/PA3, 14 ADCx_IN4/PA4, 15 T_SWCLK/PA5, 16 T_JTDO/PA6, 17 T_JTDI/PA7, 18 T_NRST/PB0, 19 T_JNRST/PB1, 20 PB2/BOOT1, 21 T_SW_DIR/PB10, 22 T_JCLK_OUT/PB11, 23 VSS, 24 VDD, 25 T_SWDIO_IN/PB12, 26 T_JRCLK/PB13, 27 T_JTMS/T_SWDIO_OUT/PB14, 28 T_PWR_EN/PB15, 29 T_MCO/PA8, 30 STLK_LED/PA9, 31 T_SWO/PA10, 32 USP_DM/PA11, 33 USP_DP/PA12, 34 STLK_SWDIO/PA13, 35 VSS, 36 VDD, 37 STLK_SWCLK/PA14, 38 USB_RENUMn/PA15, 39 T_PWR_EXT/PB3, 40 GNDDetect/PB4, 41 T_PWR_INT/PB5, 42 T_PWR_SEL1/PB6, 43 T_PWR_SEL2/PB7, 44 BOOT0, 45 PB8, 46 T_PWR_LED/PB9, 47 VSS, 48 VDD

## STLINK-V3EC
designator U?
part A pins: A6 T_JTDO/PB5, A7 STLK_VCP_TX/PG14, A10 T_JRCLK/PB3, A14 STLK_SWCLK/PA14, A15 STLK_SWDIO/PA13, C4 HW_TYP_1/PI5, C6 PDR_ON, C10 STLK_VCP_RX/PG9, C11 T_PWR_SEL2/PD5, D4 HW_TYP_0/PI4, D6 BOOT0, D10 T_PWR_SEL1/PD4, D12 T_SWO/PD2, D15 STLK_LED/PA10, F15 T_MCO/PA8, G1 OSC_IN/PH0, H1 OSC_OUT/PH1, H15 T_PWR_LED/PC6, J1 NRST, J2 T_PWR_INT/ADC3_IN9/PF3, J14 V12_OTGPHY, J15 REXT_OTGPHY, K13 GNDDetect/PG5, L2 T_JTMS/T_SWDIO_OUT/PF9, L3 T_JTDI/PF8, M5 ADCx_IN13/PC3, M6 T_JCLK_OUT/PB2, M11 T_SWCLK/PH6, N3 T_VCC AIN/PA0, N5 ADCx_IN14/PC4, N6 T_JNRST/PF13, N12 T_SWDIO_IN/PH7, P3 T_NRST/PA6, R3 T_SW_DIR/PA7, R4 T_PWR_EXT/PB1, R5 T_PWR_EN/PB0, R14 USB_DEV_HS_N/PB14, R15 USB_DEV_HS_P/PB15
part B pins: C1 VBAT, C5 VDD, C7 VDD, C8 VDD, C9 VDD, D5 VSS, D7 VSS, D8 VSS, D9 VSS, F2 VSS, F3 VDD, F6 VSS, F7 VSS, F8 VSS, F9 VSS, F10 VSS, F12 VSS, F13 VCAP2, G2 VSS, G3 VDD, G6 VSS, G7 VSS, G8 VSS, G9 VSS, G10 VSS, G12 VSS, G13 VDD, H6 VSS, H7 VSS, H8 VSS, H9 VSS, H10 VSS, H12 VSS, H13 VDD, J6 VSS, J7 VSS, J8 VSS, J9 VSS, J10 VSS, J12 VDD, J13 VDD, K4 VDD, K6 VSS, K7 VSS, K8 VSS, K9 VSS, K10 VSS, L4 BYPASS-REG, M1 VSSA, M8 VSS, M9 VSS, M10 VCAP1, N1 VREF-, N8 VDD, N9 VDD, N10 VDD, P1 VREF+, R1 VDDA
part C pins: A2 GPIO0/PE2, A5 I2C_SCL/PB8, A9 SPI_NSS/PB4, B1 GPIO1/PE4, B2 GPIO2/PE5, B3 GPIO3/PE6, B4 I2C_SDA/PB9, B14 UART_TX/PC10, B15 CAN_TX/PA12, C15 CAN_RX/PA11, E15 SPI_SCK/PA9, M3 SPI_MOSI/PC1, M4 SPI_MISO/PC2, N13 UART_RTS/PD12, N14 UART_CTS/PD11, R13 UART_RX/PB11

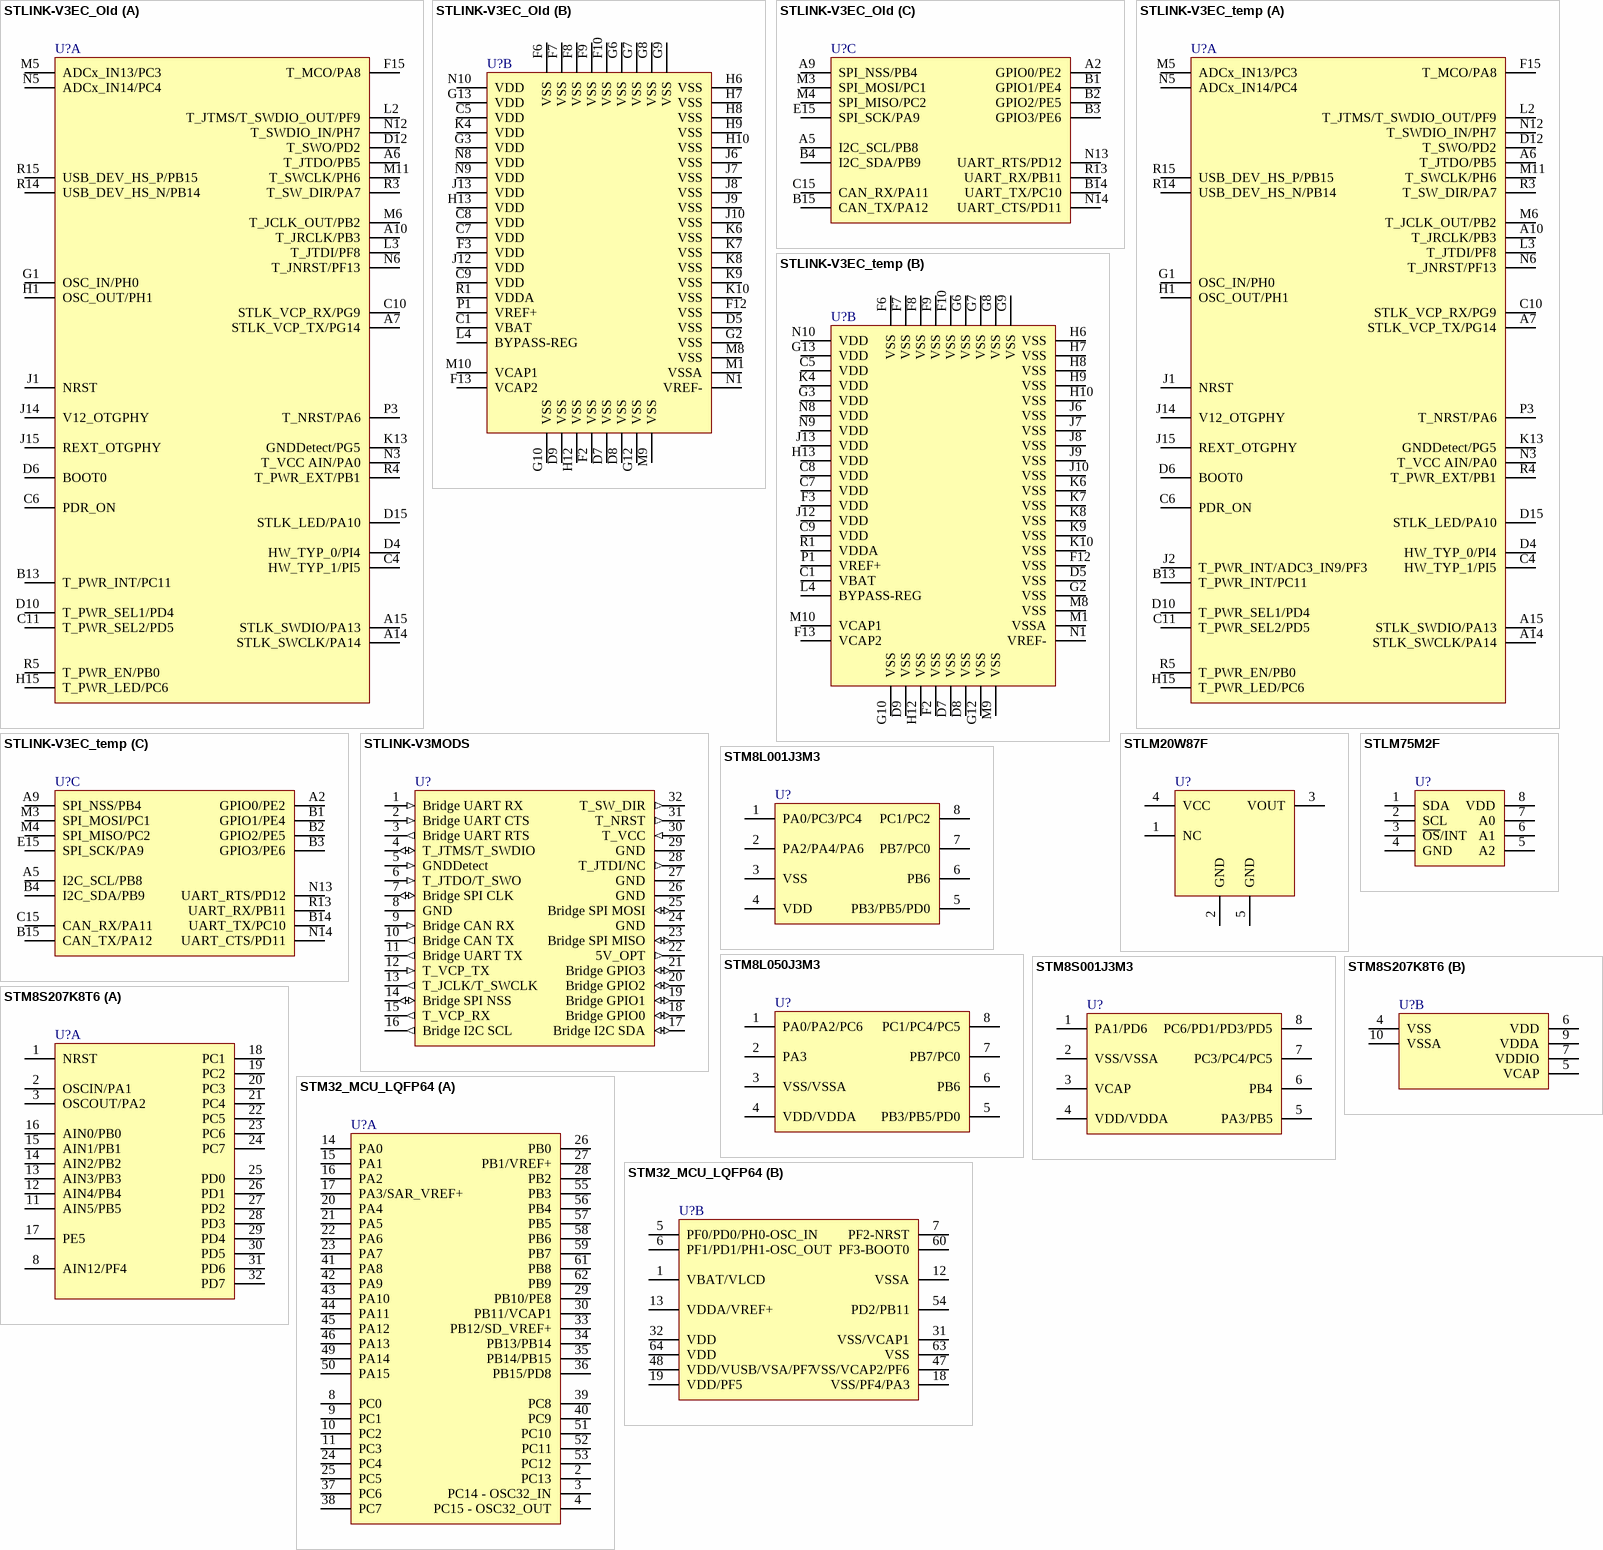
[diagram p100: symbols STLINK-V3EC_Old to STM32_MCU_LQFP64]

## STLINK-V3EC_Old
designator U?
part A pins: A6 T_JTDO/PB5, A7 STLK_VCP_TX/PG14, A10 T_JRCLK/PB3, A14 STLK_SWCLK/PA14, A15 STLK_SWDIO/PA13, B13 T_PWR_INT/PC11, C4 HW_TYP_1/PI5, C6 PDR_ON, C10 STLK_VCP_RX/PG9, C11 T_PWR_SEL2/PD5, D4 HW_TYP_0/PI4, D6 BOOT0, D10 T_PWR_SEL1/PD4, D12 T_SWO/PD2, D15 STLK_LED/PA10, F15 T_MCO/PA8, G1 OSC_IN/PH0, H1 OSC_OUT/PH1, H15 T_PWR_LED/PC6, J1 NRST, J14 V12_OTGPHY, J15 REXT_OTGPHY, K13 GNDDetect/PG5, L2 T_JTMS/T_SWDIO_OUT/PF9, L3 T_JTDI/PF8, M5 ADCx_IN13/PC3, M6 T_JCLK_OUT/PB2, M11 T_SWCLK/PH6, N3 T_VCC AIN/PA0, N5 ADCx_IN14/PC4, N6 T_JNRST/PF13, N12 T_SWDIO_IN/PH7, P3 T_NRST/PA6, R3 T_SW_DIR/PA7, R4 T_PWR_EXT/PB1, R5 T_PWR_EN/PB0, R14 USB_DEV_HS_N/PB14, R15 USB_DEV_HS_P/PB15
part B pins: C1 VBAT, C5 VDD, C7 VDD, C8 VDD, C9 VDD, D5 VSS, D7 VSS, D8 VSS, D9 VSS, F2 VSS, F3 VDD, F6 VSS, F7 VSS, F8 VSS, F9 VSS, F10 VSS, F12 VSS, F13 VCAP2, G2 VSS, G3 VDD, G6 VSS, G7 VSS, G8 VSS, G9 VSS, G10 VSS, G12 VSS, G13 VDD, H6 VSS, H7 VSS, H8 VSS, H9 VSS, H10 VSS, H12 VSS, H13 VDD, J6 VSS, J7 VSS, J8 VSS, J9 VSS, J10 VSS, J12 VDD, J13 VDD, K4 VDD, K6 VSS, K7 VSS, K8 VSS, K9 VSS, K10 VSS, L4 BYPASS-REG, M1 VSSA, M8 VSS, M9 VSS, M10 VCAP1, N1 VREF-, N8 VDD, N9 VDD, N10 VDD, P1 VREF+, R1 VDDA
part C pins: A2 GPIO0/PE2, A5 I2C_SCL/PB8, A9 SPI_NSS/PB4, B1 GPIO1/PE4, B2 GPIO2/PE5, B3 GPIO3/PE6, B4 I2C_SDA/PB9, B14 UART_TX/PC10, B15 CAN_TX/PA12, C15 CAN_RX/PA11, E15 SPI_SCK/PA9, M3 SPI_MOSI/PC1, M4 SPI_MISO/PC2, N13 UART_RTS/PD12, N14 UART_CTS/PD11, R13 UART_RX/PB11

## STLINK-V3EC_temp
designator U?
part A pins: A6 T_JTDO/PB5, A7 STLK_VCP_TX/PG14, A10 T_JRCLK/PB3, A14 STLK_SWCLK/PA14, A15 STLK_SWDIO/PA13, B13 T_PWR_INT/PC11, C4 HW_TYP_1/PI5, C6 PDR_ON, C10 STLK_VCP_RX/PG9, C11 T_PWR_SEL2/PD5, D4 HW_TYP_0/PI4, D6 BOOT0, D10 T_PWR_SEL1/PD4, D12 T_SWO/PD2, D15 STLK_LED/PA10, F15 T_MCO/PA8, G1 OSC_IN/PH0, H1 OSC_OUT/PH1, H15 T_PWR_LED/PC6, J1 NRST, J2 T_PWR_INT/ADC3_IN9/PF3, J14 V12_OTGPHY, J15 REXT_OTGPHY, K13 GNDDetect/PG5, L2 T_JTMS/T_SWDIO_OUT/PF9, L3 T_JTDI/PF8, M5 ADCx_IN13/PC3, M6 T_JCLK_OUT/PB2, M11 T_SWCLK/PH6, N3 T_VCC AIN/PA0, N5 ADCx_IN14/PC4, N6 T_JNRST/PF13, N12 T_SWDIO_IN/PH7, P3 T_NRST/PA6, R3 T_SW_DIR/PA7, R4 T_PWR_EXT/PB1, R5 T_PWR_EN/PB0, R14 USB_DEV_HS_N/PB14, R15 USB_DEV_HS_P/PB15
part B pins: C1 VBAT, C5 VDD, C7 VDD, C8 VDD, C9 VDD, D5 VSS, D7 VSS, D8 VSS, D9 VSS, F2 VSS, F3 VDD, F6 VSS, F7 VSS, F8 VSS, F9 VSS, F10 VSS, F12 VSS, F13 VCAP2, G2 VSS, G3 VDD, G6 VSS, G7 VSS, G8 VSS, G9 VSS, G10 VSS, G12 VSS, G13 VDD, H6 VSS, H7 VSS, H8 VSS, H9 VSS, H10 VSS, H12 VSS, H13 VDD, J6 VSS, J7 VSS, J8 VSS, J9 VSS, J10 VSS, J12 VDD, J13 VDD, K4 VDD, K6 VSS, K7 VSS, K8 VSS, K9 VSS, K10 VSS, L4 BYPASS-REG, M1 VSSA, M8 VSS, M9 VSS, M10 VCAP1, N1 VREF-, N8 VDD, N9 VDD, N10 VDD, P1 VREF+, R1 VDDA
part C pins: A2 GPIO0/PE2, A5 I2C_SCL/PB8, A9 SPI_NSS/PB4, B1 GPIO1/PE4, B2 GPIO2/PE5, B3 GPIO3/PE6, B4 I2C_SDA/PB9, B14 UART_TX/PC10, B15 CAN_TX/PA12, C15 CAN_RX/PA11, E15 SPI_SCK/PA9, M3 SPI_MOSI/PC1, M4 SPI_MISO/PC2, N13 UART_RTS/PD12, N14 UART_CTS/PD11, R13 UART_RX/PB11

## STLINK-V3MODS
designator U?
pins: 1 Bridge UART RX (in), 2 Bridge UART CTS (in), 3 Bridge UART RTS (out), 4 T_JTMS/T_SWDIO (io), 5 GNDDetect (in), 6 T_JTDO/T_SWO (in), 7 Bridge SPI CLK (io), 8 GND (power), 9 Bridge CAN RX (in), 10 Bridge CAN TX (out), 11 Bridge UART TX (out), 12 T_VCP_TX (in), 13 T_JCLK/T_SWCLK (out), 14 Bridge SPI NSS (io), 15 T_VCP_RX (out), 16 Bridge I2C SCL (out), 17 Bridge I2C SDA (io), 18 Bridge GPIO0 (io), 19 Bridge GPIO1 (io), 20 Bridge GPIO2 (io), 21 Bridge GPIO3 (io), 22 5V_OPT (out), 23 Bridge SPI MISO (io), 24 GND (power), 25 Bridge SPI MOSI (io), 26 GND (power), 27 GND (power), 28 T_JTDI/NC (out), 29 GND (power), 30 T_VCC (in), 31 T_NRST (out), 32 T_SW_DIR (out)

## STLM20W87F
designator U?
pins: 1 NC, 2 GND, 3 VOUT, 4 VCC, 5 GND

## STLM75M2F
designator U?
pins: 1 SDA, 2 SCL, 3 ~{OS}/INT, 4 GND, 5 A2, 6 A1, 7 A0, 8 VDD

## STM8L001J3M3
designator U?
pins: 1 PA0/PC3/PC4, 2 PA2/PA4/PA6, 3 VSS, 4 VDD, 5 PB3/PB5/PD0, 6 PB6, 7 PB7/PC0, 8 PC1/PC2

## STM8L050J3M3
designator U?
pins: 1 PA0/PA2/PC6, 2 PA3, 3 VSS/VSSA, 4 VDD/VDDA, 5 PB3/PB5/PD0, 6 PB6, 7 PB7/PC0, 8 PC1/PC4/PC5

## STM8S001J3M3
designator U?
pins: 1 PA1/PD6, 2 VSS/VSSA, 3 VCAP, 4 VDD/VDDA, 5 PA3/PB5, 6 PB4, 7 PC3/PC4/PC5, 8 PC6/PD1/PD3/PD5

## STM8S207K8T6
designator U?
part A pins: 1 NRST, 2 OSCIN/PA1, 3 OSCOUT/PA2, 8 AIN12/PF4, 11 AIN5/PB5, 12 AIN4/PB4, 13 AIN3/PB3, 14 AIN2/PB2, 15 AIN1/PB1, 16 AIN0/PB0, 17 PE5, 18 PC1, 19 PC2, 20 PC3, 21 PC4, 22 PC5, 23 PC6, 24 PC7, 25 PD0, 26 PD1, 27 PD2, 28 PD3, 29 PD4, 30 PD5, 31 PD6, 32 PD7
part B pins: 4 VSS, 5 VCAP, 6 VDD, 7 VDDIO, 9 VDDA, 10 VSSA

## STM32_MCU_LQFP64
designator U?
part A pins: 2 PC13, 3 PC14 - OSC32_IN, 4 PC15 - OSC32_OUT, 8 PC0, 9 PC1, 10 PC2, 11 PC3, 14 PA0, 15 PA1, 16 PA2, 17 PA3/SAR_VREF+, 20 PA4, 21 PA5, 22 PA6, 23 PA7, 24 PC4, 25 PC5, 26 PB0, 27 PB1/VREF+, 28 PB2, 29 PB10/PE8, 30 PB11/VCAP1, 33 PB12/SD_VREF+, 34 PB13/PB14, 35 PB14/PB15, 36 PB15/PD8, 37 PC6, 38 PC7, 39 PC8, 40 PC9, 41 PA8, 42 PA9, 43 PA10, 44 PA11, 45 PA12, 46 PA13, 49 PA14, 50 PA15, 51 PC10, 52 PC11, 53 PC12, 55 PB3, 56 PB4, 57 PB5, 58 PB6, 59 PB7, 61 PB8, 62 PB9
part B pins: 1 VBAT/VLCD, 5 PF0/PD0/PH0-OSC_IN, 6 PF1/PD1/PH1-OSC_OUT, 7 PF2-NRST, 12 VSSA, 13 VDDA/VREF+, 18 VSS/PF4/PA3, 19 VDD/PF5, 31 VSS/VCAP1, 32 VDD, 47 VSS/VCAP2/PF6, 48 VDD/VUSB/VSA/PF7, 54 PD2/PB11, 60 PF3-BOOT0, 63 VSS, 64 VDD

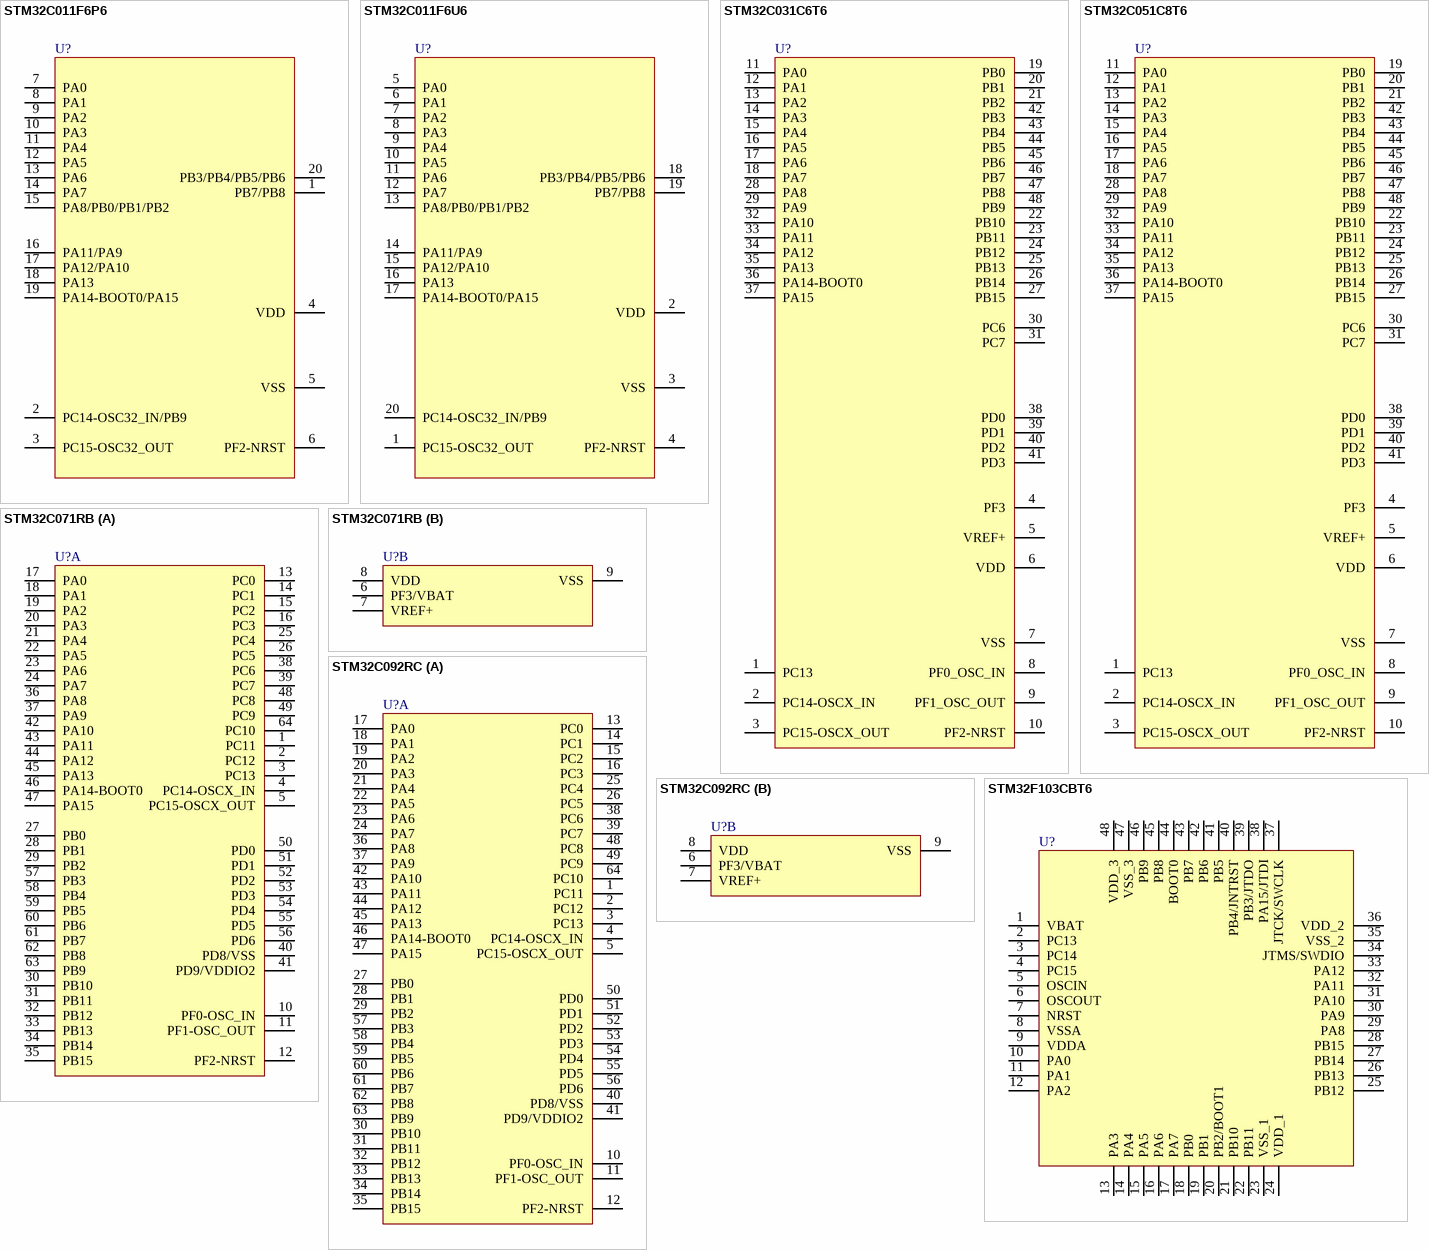
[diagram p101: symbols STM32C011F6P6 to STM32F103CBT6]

## STM32C011F6P6
designator U?
pins: 1 PB7/PB8, 2 PC14-OSC32_IN/PB9, 3 PC15-OSC32_OUT, 4 VDD, 5 VSS, 6 PF2-NRST, 7 PA0, 8 PA1, 9 PA2, 10 PA3, 11 PA4, 12 PA5, 13 PA6, 14 PA7, 15 PA8/PB0/PB1/PB2, 16 PA11/PA9, 17 PA12/PA10, 18 PA13, 19 PA14-BOOT0/PA15, 20 PB3/PB4/PB5/PB6

## STM32C011F6U6
designator U?
pins: 1 PC15-OSC32_OUT, 2 VDD, 3 VSS, 4 PF2-NRST, 5 PA0, 6 PA1, 7 PA2, 8 PA3, 9 PA4, 10 PA5, 11 PA6, 12 PA7, 13 PA8/PB0/PB1/PB2, 14 PA11/PA9, 15 PA12/PA10, 16 PA13, 17 PA14-BOOT0/PA15, 18 PB3/PB4/PB5/PB6, 19 PB7/PB8, 20 PC14-OSC32_IN/PB9

## STM32C031C6T6
designator U?
pins: 1 PC13, 2 PC14-OSCX_IN, 3 PC15-OSCX_OUT, 4 PF3, 5 VREF+, 6 VDD, 7 VSS, 8 PF0_OSC_IN, 9 PF1_OSC_OUT, 10 PF2-NRST, 11 PA0, 12 PA1, 13 PA2, 14 PA3, 15 PA4, 16 PA5, 17 PA6, 18 PA7, 19 PB0, 20 PB1, 21 PB2, 22 PB10, 23 PB11, 24 PB12, 25 PB13, 26 PB14, 27 PB15, 28 PA8, 29 PA9, 30 PC6, 31 PC7, 32 PA10, 33 PA11, 34 PA12, 35 PA13, 36 PA14-BOOT0, 37 PA15, 38 PD0, 39 PD1, 40 PD2, 41 PD3, 42 PB3, 43 PB4, 44 PB5, 45 PB6, 46 PB7, 47 PB8, 48 PB9

## STM32C051C8T6
designator U?
pins: 1 PC13, 2 PC14-OSCX_IN, 3 PC15-OSCX_OUT, 4 PF3, 5 VREF+, 6 VDD, 7 VSS, 8 PF0_OSC_IN, 9 PF1_OSC_OUT, 10 PF2-NRST, 11 PA0, 12 PA1, 13 PA2, 14 PA3, 15 PA4, 16 PA5, 17 PA6, 18 PA7, 19 PB0, 20 PB1, 21 PB2, 22 PB10, 23 PB11, 24 PB12, 25 PB13, 26 PB14, 27 PB15, 28 PA8, 29 PA9, 30 PC6, 31 PC7, 32 PA10, 33 PA11, 34 PA12, 35 PA13, 36 PA14-BOOT0, 37 PA15, 38 PD0, 39 PD1, 40 PD2, 41 PD3, 42 PB3, 43 PB4, 44 PB5, 45 PB6, 46 PB7, 47 PB8, 48 PB9

## STM32C071RB
designator U?
part A pins: 1 PC11, 2 PC12, 3 PC13, 4 PC14-OSCX_IN, 5 PC15-OSCX_OUT, 10 PF0-OSC_IN, 11 PF1-OSC_OUT, 12 PF2-NRST, 13 PC0, 14 PC1, 15 PC2, 16 PC3, 17 PA0, 18 PA1, 19 PA2, 20 PA3, 21 PA4, 22 PA5, 23 PA6, 24 PA7, 25 PC4, 26 PC5, 27 PB0, 28 PB1, 29 PB2, 30 PB10, 31 PB11, 32 PB12, 33 PB13, 34 PB14, 35 PB15, 36 PA8, 37 PA9, 38 PC6, 39 PC7, 40 PD8/VSS, 41 PD9/VDDIO2, 42 PA10, 43 PA11, 44 PA12, 45 PA13, 46 PA14-BOOT0, 47 PA15, 48 PC8, 49 PC9, 50 PD0, 51 PD1, 52 PD2, 53 PD3, 54 PD4, 55 PD5, 56 PD6, 57 PB3, 58 PB4, 59 PB5, 60 PB6, 61 PB7, 62 PB8, 63 PB9, 64 PC10
part B pins: 6 PF3/VBAT (power), 7 VREF+ (power), 8 VDD (power), 9 VSS

## STM32C092RC
designator U?
part A pins: 1 PC11, 2 PC12, 3 PC13, 4 PC14-OSCX_IN, 5 PC15-OSCX_OUT, 10 PF0-OSC_IN, 11 PF1-OSC_OUT, 12 PF2-NRST, 13 PC0, 14 PC1, 15 PC2, 16 PC3, 17 PA0, 18 PA1, 19 PA2, 20 PA3, 21 PA4, 22 PA5, 23 PA6, 24 PA7, 25 PC4, 26 PC5, 27 PB0, 28 PB1, 29 PB2, 30 PB10, 31 PB11, 32 PB12, 33 PB13, 34 PB14, 35 PB15, 36 PA8, 37 PA9, 38 PC6, 39 PC7, 40 PD8/VSS, 41 PD9/VDDIO2, 42 PA10, 43 PA11, 44 PA12, 45 PA13, 46 PA14-BOOT0, 47 PA15, 48 PC8, 49 PC9, 50 PD0, 51 PD1, 52 PD2, 53 PD3, 54 PD4, 55 PD5, 56 PD6, 57 PB3, 58 PB4, 59 PB5, 60 PB6, 61 PB7, 62 PB8, 63 PB9, 64 PC10
part B pins: 6 PF3/VBAT (power), 7 VREF+ (power), 8 VDD (power), 9 VSS

## STM32F103CBT6
designator U?
pins: 1 VBAT, 2 PC13, 3 PC14, 4 PC15, 5 OSCIN, 6 OSCOUT, 7 NRST, 8 VSSA, 9 VDDA, 10 PA0, 11 PA1, 12 PA2, 13 PA3, 14 PA4, 15 PA5, 16 PA6, 17 PA7, 18 PB0, 19 PB1, 20 PB2/BOOT1, 21 PB10, 22 PB11, 23 VSS_1, 24 VDD_1, 25 PB12, 26 PB13, 27 PB14, 28 PB15, 29 PA8, 30 PA9, 31 PA10, 32 PA11, 33 PA12, 34 JTMS/SWDIO, 35 VSS_2, 36 VDD_2, 37 JTCK/SWCLK, 38 PA15/JTDI, 39 PB3/JTDO, 40 PB4/JNTRST, 41 PB5, 42 PB6, 43 PB7, 44 BOOT0, 45 PB8, 46 PB9, 47 VSS_3, 48 VDD_3

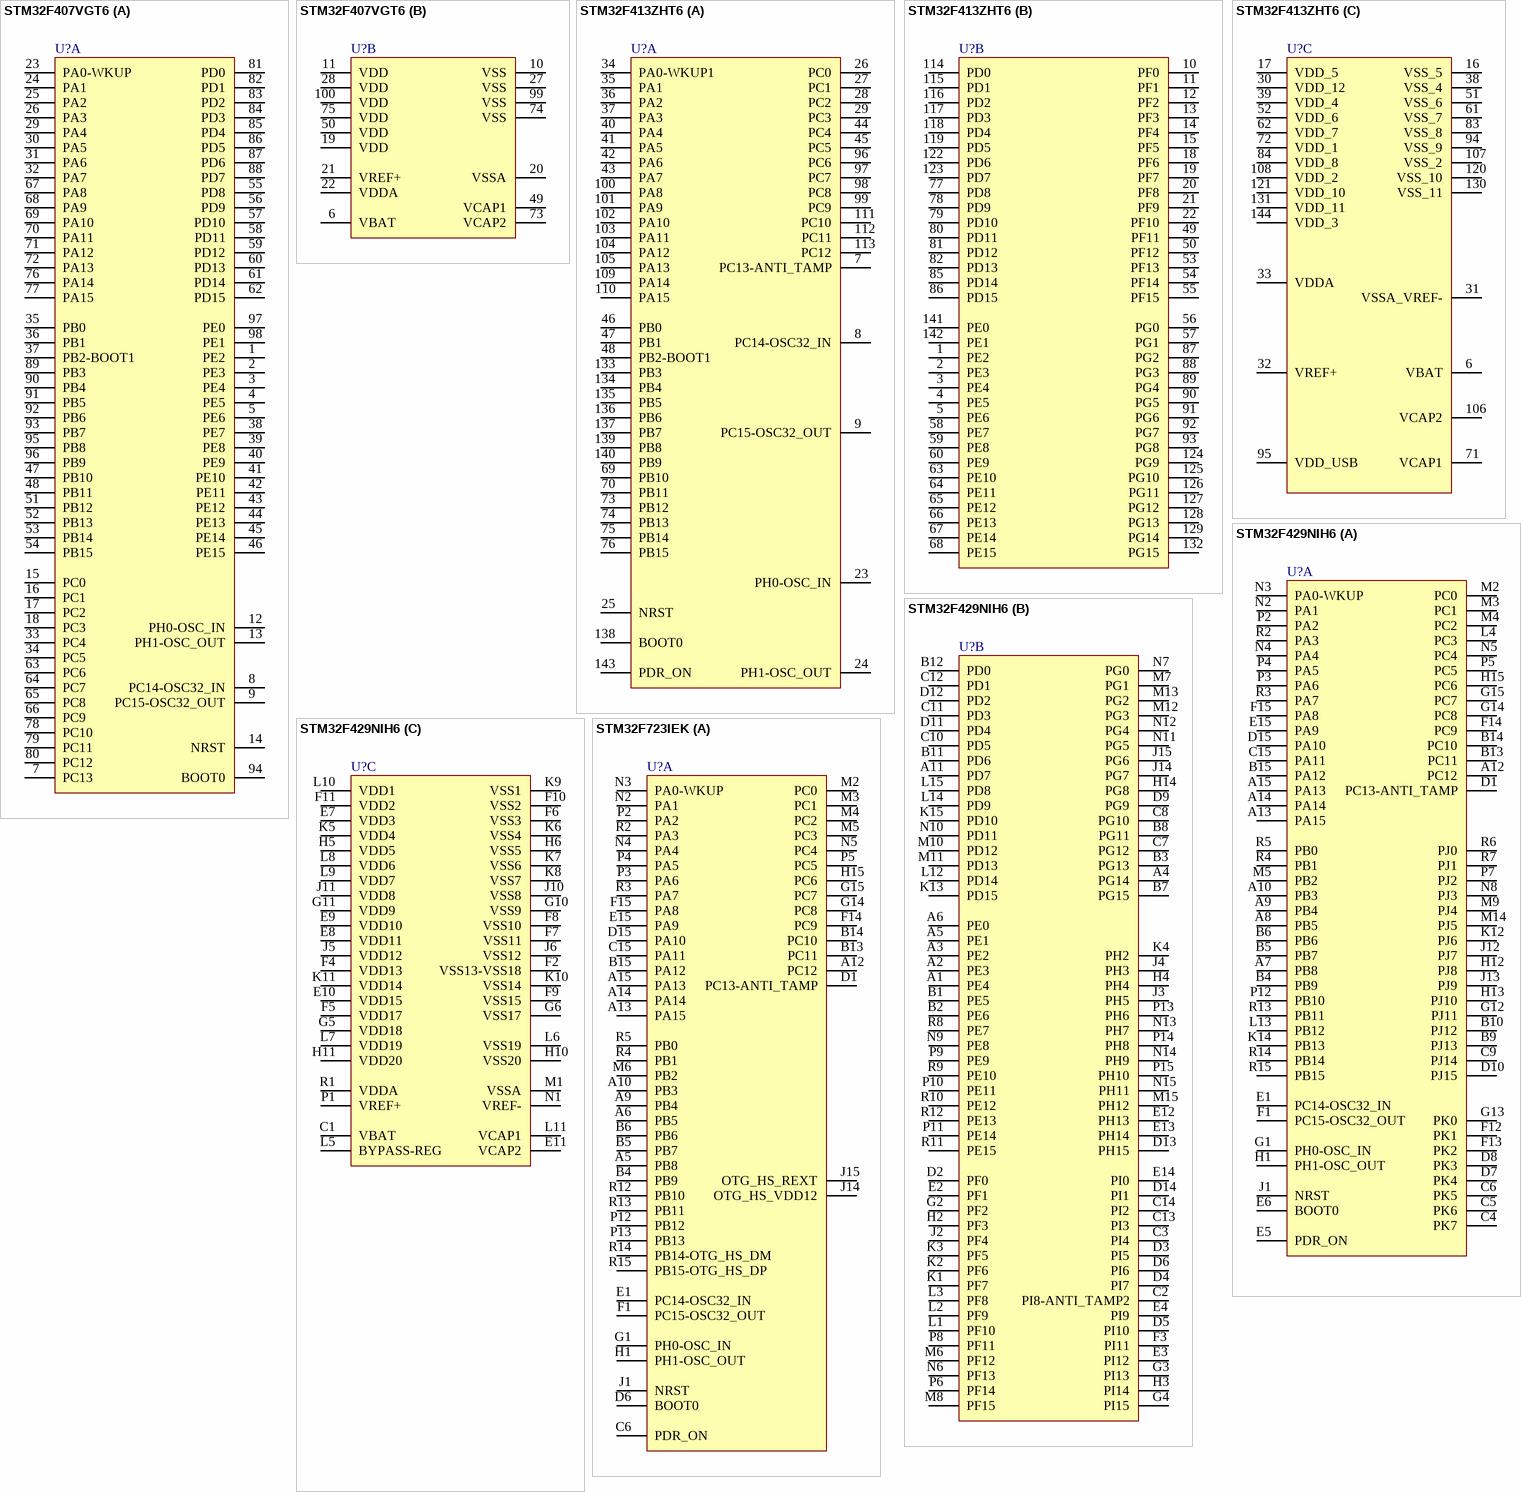
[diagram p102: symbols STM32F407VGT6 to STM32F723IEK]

## STM32F407VGT6
designator U?
part A pins: 1 PE2, 2 PE3, 3 PE4, 4 PE5, 5 PE6, 7 PC13, 8 PC14-OSC32_IN, 9 PC15-OSC32_OUT, 12 PH0-OSC_IN, 13 PH1-OSC_OUT, 14 NRST, 15 PC0, 16 PC1, 17 PC2, 18 PC3, 23 PA0-WKUP, 24 PA1, 25 PA2, 26 PA3, 29 PA4, 30 PA5, 31 PA6, 32 PA7, 33 PC4, 34 PC5, 35 PB0, 36 PB1, 37 PB2-BOOT1, 38 PE7, 39 PE8, 40 PE9, 41 PE10, 42 PE11, 43 PE12, 44 PE13, 45 PE14, 46 PE15, 47 PB10, 48 PB11, 51 PB12, 52 PB13, 53 PB14, 54 PB15, 55 PD8, 56 PD9, 57 PD10, 58 PD11, 59 PD12, 60 PD13, 61 PD14, 62 PD15, 63 PC6, 64 PC7, 65 PC8, 66 PC9, 67 PA8, 68 PA9, 69 PA10, 70 PA11, 71 PA12, 72 PA13, 76 PA14, 77 PA15, 78 PC10, 79 PC11, 80 PC12, 81 PD0, 82 PD1, 83 PD2, 84 PD3, 85 PD4, 86 PD5, 87 PD6, 88 PD7, 89 PB3, 90 PB4, 91 PB5, 92 PB6, 93 PB7, 94 BOOT0, 95 PB8, 96 PB9, 97 PE0, 98 PE1
part B pins: 6 VBAT, 10 VSS, 11 VDD, 19 VDD, 20 VSSA, 21 VREF+, 22 VDDA, 27 VSS, 28 VDD, 49 VCAP1, 50 VDD, 73 VCAP2, 74 VSS, 75 VDD, 99 VSS, 100 VDD

## STM32F413ZHT6
designator U?
part A pins: 7 PC13-ANTI_TAMP, 8 PC14-OSC32_IN, 9 PC15-OSC32_OUT, 23 PH0-OSC_IN, 24 PH1-OSC_OUT, 25 NRST, 26 PC0, 27 PC1, 28 PC2, 29 PC3, 34 PA0-WKUP1, 35 PA1, 36 PA2, 37 PA3, 40 PA4, 41 PA5, 42 PA6, 43 PA7, 44 PC4, 45 PC5, 46 PB0, 47 PB1, 48 PB2-BOOT1, 69 PB10, 70 PB11, 73 PB12, 74 PB13, 75 PB14, 76 PB15, 96 PC6, 97 PC7, 98 PC8, 99 PC9, 100 PA8, 101 PA9, 102 PA10, 103 PA11, 104 PA12, 105 PA13, 109 PA14, 110 PA15, 111 PC10, 112 PC11, 113 PC12, 133 PB3, 134 PB4, 135 PB5, 136 PB6, 137 PB7, 138 BOOT0, 139 PB8, 140 PB9, 143 PDR_ON
part B pins: 1 PE2, 2 PE3, 3 PE4, 4 PE5, 5 PE6, 10 PF0, 11 PF1, 12 PF2, 13 PF3, 14 PF4, 15 PF5, 18 PF6, 19 PF7, 20 PF8, 21 PF9, 22 PF10, 49 PF11, 50 PF12, 53 PF13, 54 PF14, 55 PF15, 56 PG0, 57 PG1, 58 PE7, 59 PE8, 60 PE9, 63 PE10, 64 PE11, 65 PE12, 66 PE13, 67 PE14, 68 PE15, 77 PD8, 78 PD9, 79 PD10, 80 PD11, 81 PD12, 82 PD13, 85 PD14, 86 PD15, 87 PG2, 88 PG3, 89 PG4, 90 PG5, 91 PG6, 92 PG7, 93 PG8, 114 PD0, 115 PD1, 116 PD2, 117 PD3, 118 PD4, 119 PD5, 122 PD6, 123 PD7, 124 PG9, 125 PG10, 126 PG11, 127 PG12, 128 PG13, 129 PG14, 132 PG15, 141 PE0, 142 PE1
part C pins: 6 VBAT, 16 VSS_5, 17 VDD_5, 30 VDD_12, 31 VSSA_VREF-, 32 VREF+, 33 VDDA, 38 VSS_4, 39 VDD_4, 51 VSS_6, 52 VDD_6, 61 VSS_7, 62 VDD_7, 71 VCAP1, 72 VDD_1, 83 VSS_8, 84 VDD_8, 94 VSS_9, 95 VDD_USB, 106 VCAP2, 107 VSS_2, 108 VDD_2, 120 VSS_10, 121 VDD_10, 130 VSS_11, 131 VDD_11, 144 VDD_3

## STM32F429NIH6
designator U?
part A pins: A7 PB8, A8 PB5, A9 PB4, A10 PB3, A12 PC12, A13 PA15, A14 PA14, A15 PA13, B4 PB9, B5 PB7, B6 PB6, B9 PJ13, B10 PJ12, B13 PC11, B14 PC10, B15 PA12, C4 PK7, C5 PK6, C6 PK5, C9 PJ14, C15 PA11, D1 PC13-ANTI_TAMP, D7 PK4, D8 PK3, D10 PJ15, D15 PA10, E1 PC14-OSC32_IN, E5 PDR_ON, E6 BOOT0, E15 PA9, F1 PC15-OSC32_OUT, F12 PK1, F13 PK2, F14 PC9, F15 PA8, G1 PH0-OSC_IN, G12 PJ11, G13 PK0, G14 PC8, G15 PC7, H1 PH1-OSC_OUT, H12 PJ8, H13 PJ10, H15 PC6, J1 NRST, J12 PJ7, J13 PJ9, K12 PJ6, K14 PB13, L4 PC3, L13 PB12, M2 PC0, M3 PC1, M4 PC2, M5 PB2, M9 PJ4, M14 PJ5, N2 PA1, N3 PA0-WKUP, N4 PA4, N5 PC4, N8 PJ3, P2 PA2, P3 PA6, P4 PA5, P5 PC5, P7 PJ2, P12 PB10, R2 PA3, R3 PA7, R4 PB1, R5 PB0, R6 PJ0, R7 PJ1, R13 PB11, R14 PB14, R15 PB15
part B pins: A1 PE4, A2 PE3, A3 PE2, A4 PG14, A5 PE1, A6 PE0, A11 PD7, B1 PE5, B2 PE6, B3 PG13, B7 PG15, B8 PG11, B11 PD6, B12 PD0, C2 PI8-ANTI_TAMP2, C3 PI4, C7 PG12, C8 PG10, C10 PD5, C11 PD3, C12 PD1, C13 PI3, C14 PI2, D2 PF0, D3 PI5, D4 PI7, D5 PI10, D6 PI6, D9 PG9, D11 PD4, D12 PD2, D13 PH15, D14 PI1, E2 PF1, E3 PI12, E4 PI9, E12 PH13, E13 PH14, E14 PI0, F3 PI11, G2 PF2, G3 PI13, G4 PI15, H2 PF3, H3 PI14, H4 PH4, H14 PG8, J2 PF4, J3 PH5, J4 PH3, J14 PG7, J15 PG6, K1 PF7, K2 PF6, K3 PF5, K4 PH2, K13 PD15, K15 PD10, L1 PF10, L2 PF9, L3 PF8, L12 PD14, L14 PD9, L15 PD8, M6 PF12, M7 PG1, M8 PF15, M10 PD12, M11 PD13, M12 PG3, M13 PG2, M15 PH12, N6 PF13, N7 PG0, N9 PE8, N10 PD11, N11 PG5, N12 PG4, N13 PH7, N14 PH9, N15 PH11, P6 PF14, P8 PF11, P9 PE9, P10 PE11, P11 PE14, P13 PH6, P14 PH8, P15 PH10, R8 PE7, R9 PE10, R10 PE12, R11 PE15, R12 PE13
part C pins: C1 VBAT, E7 VDD3, E8 VDD11, E9 VDD10, E10 VDD15, E11 VCAP2, F2 VSS13-VSS18, F4 VDD13, F5 VDD17, F6 VSS3, F7 VSS11, F8 VSS10, F9 VSS15, F10 VSS2, F11 VDD2, G5 VDD18, G6 VSS17, G10 VSS9, G11 VDD9, H5 VDD5, H6 VSS5, H10 VSS20, H11 VDD20, J5 VDD12, J6 VSS12, J10 VSS8, J11 VDD8, K5 VDD4, K6 VSS4, K7 VSS6, K8 VSS7, K9 VSS1, K10 VSS14, K11 VDD14, L5 BYPASS-REG, L6 VSS19, L7 VDD19, L8 VDD6, L9 VDD7, L10 VDD1, L11 VCAP1, M1 VSSA, N1 VREF-, P1 VREF+, R1 VDDA
2 alternate drawings of the same symbol

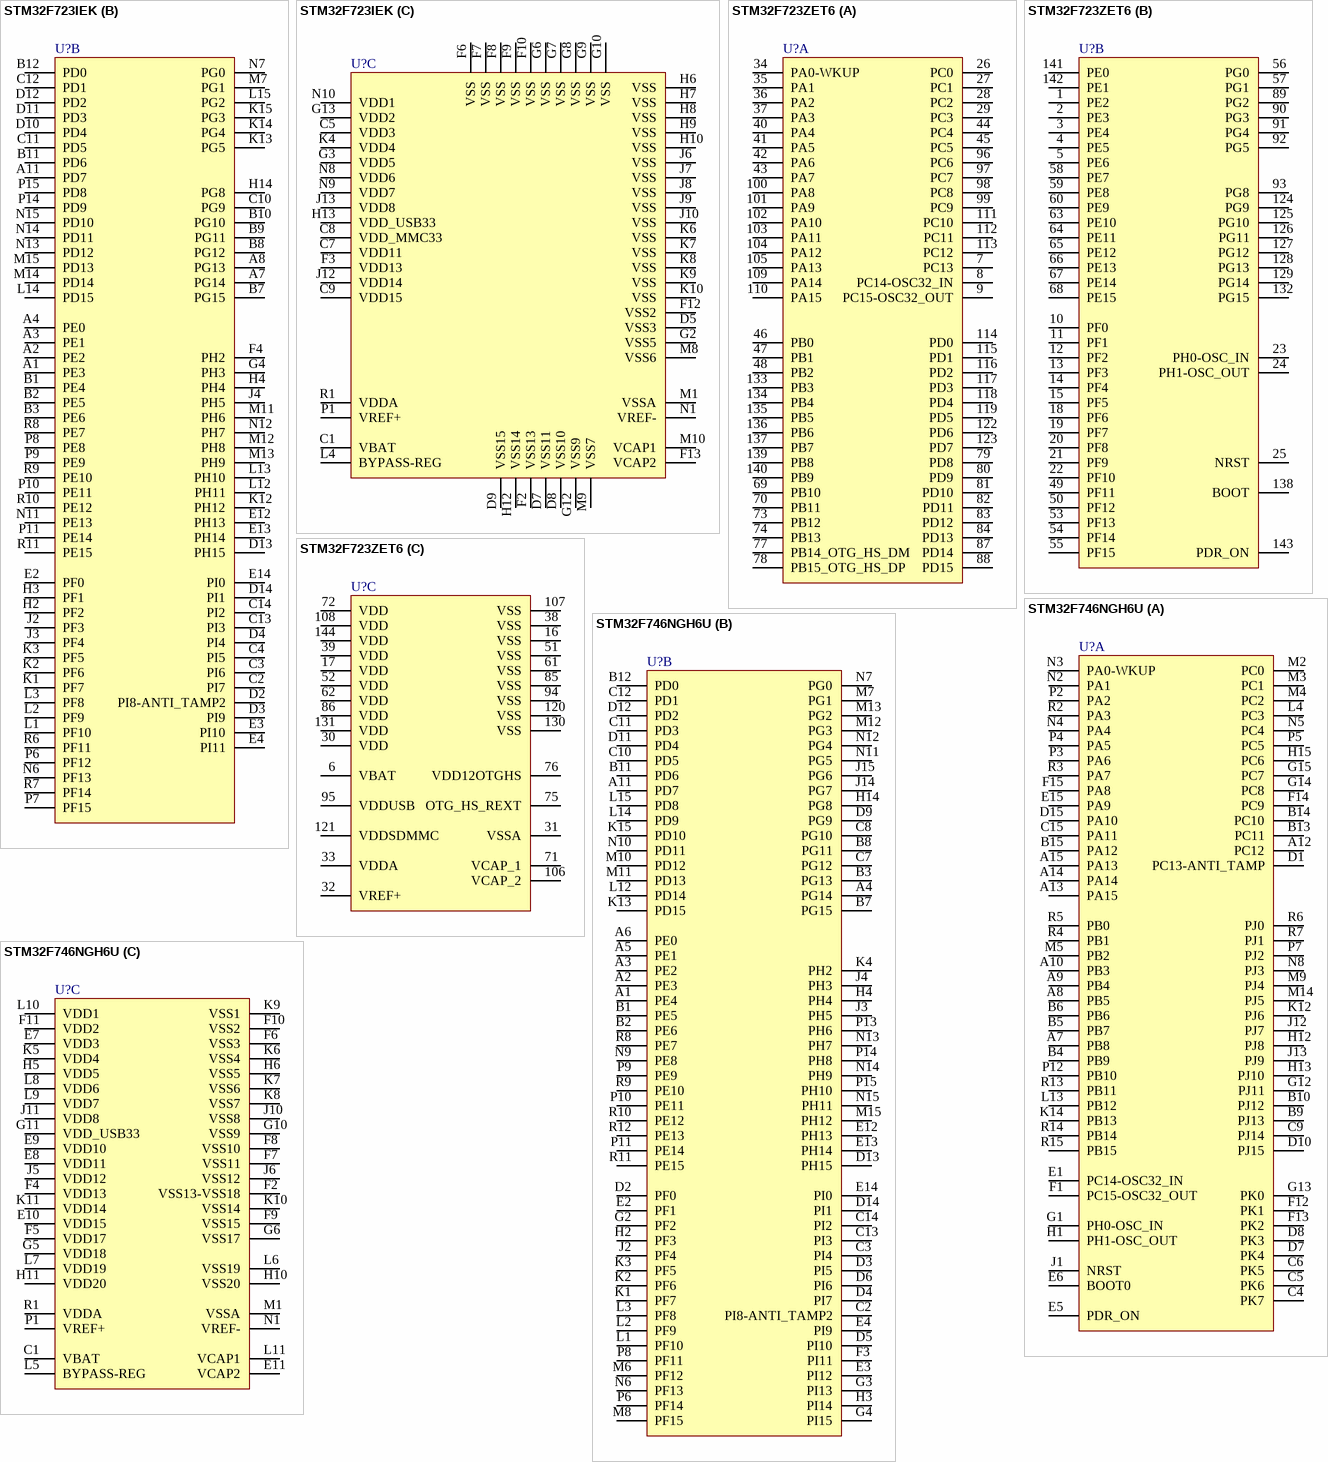
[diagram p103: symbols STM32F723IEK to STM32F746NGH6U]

## STM32F723IEK
designator U?
part A pins: A5 PB8, A6 PB5, A9 PB4, A10 PB3, A12 PC12, A13 PA15, A14 PA14, A15 PA13, B4 PB9, B5 PB7, B6 PB6, B13 PC11, B14 PC10, B15 PA12, C6 PDR_ON, C15 PA11, D1 PC13-ANTI_TAMP, D6 BOOT0, D15 PA10, E1 PC14-OSC32_IN, E15 PA9, F1 PC15-OSC32_OUT, F14 PC9, F15 PA8, G1 PH0-OSC_IN, G14 PC8, G15 PC7, H1 PH1-OSC_OUT, H15 PC6, J1 NRST, J14 OTG_HS_VDD12, J15 OTG_HS_REXT, M2 PC0, M3 PC1, M4 PC2, M5 PC3, M6 PB2, N2 PA1, N3 PA0-WKUP, N4 PA4, N5 PC4, P2 PA2, P3 PA6, P4 PA5, P5 PC5, P12 PB12, P13 PB13, R2 PA3, R3 PA7, R4 PB1, R5 PB0, R12 PB10, R13 PB11, R14 PB14-OTG_HS_DM, R15 PB15-OTG_HS_DP
part B pins: A1 PE3, A2 PE2, A3 PE1, A4 PE0, A7 PG14, A8 PG13, A11 PD7, B1 PE4, B2 PE5, B3 PE6, B7 PG15, B8 PG12, B9 PG11, B10 PG10, B11 PD6, B12 PD0, C2 PI7, C3 PI6, C4 PI5, C10 PG9, C11 PD5, C12 PD1, C13 PI3, C14 PI2, D2 PI8-ANTI_TAMP2, D3 PI9, D4 PI4, D10 PD4, D11 PD3, D12 PD2, D13 PH15, D14 PI1, E2 PF0, E3 PI10, E4 PI11, E12 PH13, E13 PH14, E14 PI0, F4 PH2, G4 PH3, H2 PF2, H3 PF1, H4 PH4, H14 PG8, J2 PF3, J3 PF4, J4 PH5, K1 PF7, K2 PF6, K3 PF5, K12 PH12, K13 PG5, K14 PG4, K15 PG3, L1 PF10, L2 PF9, L3 PF8, L12 PH11, L13 PH10, L14 PD15, L15 PG2, M7 PG1, M11 PH6, M12 PH8, M13 PH9, M14 PD14, M15 PD13, N6 PF13, N7 PG0, N11 PE13, N12 PH7, N13 PD12, N14 PD11, N15 PD10, P6 PF12, P7 PF15, P8 PE8, P9 PE9, P10 PE11, P11 PE14, P14 PD9, P15 PD8, R6 PF11, R7 PF14, R8 PE7, R9 PE10, R10 PE12, R11 PE15
part C pins: C1 VBAT, C5 VDD3, C7 VDD11, C8 VDD_MMC33, C9 VDD15, D5 VSS3, D7 VSS11, D8 VSS10, D9 VSS15, F2 VSS13, F3 VDD13, F6 VSS, F7 VSS, F8 VSS, F9 VSS, F10 VSS, F12 VSS2, F13 VCAP2, G2 VSS5, G3 VDD5, G6 VSS, G7 VSS, G8 VSS, G9 VSS, G10 VSS, G12 VSS9, G13 VDD2, H6 VSS, H7 VSS, H8 VSS, H9 VSS, H10 VSS, H12 VSS14, H13 VDD_USB33, J6 VSS, J7 VSS, J8 VSS, J9 VSS, J10 VSS, J12 VDD14, J13 VDD8, K4 VDD4, K6 VSS, K7 VSS, K8 VSS, K9 VSS, K10 VSS, L4 BYPASS-REG, M1 VSSA, M8 VSS6, M9 VSS7, M10 VCAP1, N1 VREF-, N8 VDD6, N9 VDD7, N10 VDD1, P1 VREF+, R1 VDDA

## STM32F723ZET6
designator U?
part A pins: 7 PC13, 8 PC14-OSC32_IN, 9 PC15-OSC32_OUT, 26 PC0, 27 PC1, 28 PC2, 29 PC3, 34 PA0-WKUP, 35 PA1, 36 PA2, 37 PA3, 40 PA4, 41 PA5, 42 PA6, 43 PA7, 44 PC4, 45 PC5, 46 PB0, 47 PB1, 48 PB2, 69 PB10, 70 PB11, 73 PB12, 74 PB13, 77 PB14_OTG_HS_DM, 78 PB15_OTG_HS_DP, 79 PD8, 80 PD9, 81 PD10, 82 PD11, 83 PD12, 84 PD13, 87 PD14, 88 PD15, 96 PC6, 97 PC7, 98 PC8, 99 PC9, 100 PA8, 101 PA9, 102 PA10, 103 PA11, 104 PA12, 105 PA13, 109 PA14, 110 PA15, 111 PC10, 112 PC11, 113 PC12, 114 PD0, 115 PD1, 116 PD2, 117 PD3, 118 PD4, 119 PD5, 122 PD6, 123 PD7, 133 PB3, 134 PB4, 135 PB5, 136 PB6, 137 PB7, 139 PB8, 140 PB9
part B pins: 1 PE2, 2 PE3, 3 PE4, 4 PE5, 5 PE6, 10 PF0, 11 PF1, 12 PF2, 13 PF3, 14 PF4, 15 PF5, 18 PF6, 19 PF7, 20 PF8, 21 PF9, 22 PF10, 23 PH0-OSC_IN, 24 PH1-OSC_OUT, 25 NRST, 49 PF11, 50 PF12, 53 PF13, 54 PF14, 55 PF15, 56 PG0, 57 PG1, 58 PE7, 59 PE8, 60 PE9, 63 PE10, 64 PE11, 65 PE12, 66 PE13, 67 PE14, 68 PE15, 89 PG2, 90 PG3, 91 PG4, 92 PG5, 93 PG8, 124 PG9, 125 PG10, 126 PG11, 127 PG12, 128 PG13, 129 PG14, 132 PG15, 138 BOOT, 141 PE0, 142 PE1, 143 PDR_ON
part C pins: 6 VBAT, 16 VSS, 17 VDD, 30 VDD, 31 VSSA, 32 VREF+, 33 VDDA, 38 VSS, 39 VDD, 51 VSS, 52 VDD, 61 VSS, 62 VDD, 71 VCAP_1, 72 VDD, 75 OTG_HS_REXT, 76 VDD12OTGHS, 85 VSS, 86 VDD, 94 VSS, 95 VDDUSB, 106 VCAP_2, 107 VSS, 108 VDD, 120 VSS, 121 VDDSDMMC, 130 VSS, 131 VDD, 144 VDD

## STM32F746NGH6U
designator U?
part A pins: A7 PB8, A8 PB5, A9 PB4, A10 PB3, A12 PC12, A13 PA15, A14 PA14, A15 PA13, B4 PB9, B5 PB7, B6 PB6, B9 PJ13, B10 PJ12, B13 PC11, B14 PC10, B15 PA12, C4 PK7, C5 PK6, C6 PK5, C9 PJ14, C15 PA11, D1 PC13-ANTI_TAMP, D7 PK4, D8 PK3, D10 PJ15, D15 PA10, E1 PC14-OSC32_IN, E5 PDR_ON, E6 BOOT0, E15 PA9, F1 PC15-OSC32_OUT, F12 PK1, F13 PK2, F14 PC9, F15 PA8, G1 PH0-OSC_IN, G12 PJ11, G13 PK0, G14 PC8, G15 PC7, H1 PH1-OSC_OUT, H12 PJ8, H13 PJ10, H15 PC6, J1 NRST, J12 PJ7, J13 PJ9, K12 PJ6, K14 PB13, L4 PC3, L13 PB12, M2 PC0, M3 PC1, M4 PC2, M5 PB2, M9 PJ4, M14 PJ5, N2 PA1, N3 PA0-WKUP, N4 PA4, N5 PC4, N8 PJ3, P2 PA2, P3 PA6, P4 PA5, P5 PC5, P7 PJ2, P12 PB10, R2 PA3, R3 PA7, R4 PB1, R5 PB0, R6 PJ0, R7 PJ1, R13 PB11, R14 PB14, R15 PB15
part B pins: A1 PE4, A2 PE3, A3 PE2, A4 PG14, A5 PE1, A6 PE0, A11 PD7, B1 PE5, B2 PE6, B3 PG13, B7 PG15, B8 PG11, B11 PD6, B12 PD0, C2 PI8-ANTI_TAMP2, C3 PI4, C7 PG12, C8 PG10, C10 PD5, C11 PD3, C12 PD1, C13 PI3, C14 PI2, D2 PF0, D3 PI5, D4 PI7, D5 PI10, D6 PI6, D9 PG9, D11 PD4, D12 PD2, D13 PH15, D14 PI1, E2 PF1, E3 PI12, E4 PI9, E12 PH13, E13 PH14, E14 PI0, F3 PI11, G2 PF2, G3 PI13, G4 PI15, H2 PF3, H3 PI14, H4 PH4, H14 PG8, J2 PF4, J3 PH5, J4 PH3, J14 PG7, J15 PG6, K1 PF7, K2 PF6, K3 PF5, K4 PH2, K13 PD15, K15 PD10, L1 PF10, L2 PF9, L3 PF8, L12 PD14, L14 PD9, L15 PD8, M6 PF12, M7 PG1, M8 PF15, M10 PD12, M11 PD13, M12 PG3, M13 PG2, M15 PH12, N6 PF13, N7 PG0, N9 PE8, N10 PD11, N11 PG5, N12 PG4, N13 PH7, N14 PH9, N15 PH11, P6 PF14, P8 PF11, P9 PE9, P10 PE11, P11 PE14, P13 PH6, P14 PH8, P15 PH10, R8 PE7, R9 PE10, R10 PE12, R11 PE15, R12 PE13
part C pins: C1 VBAT, E7 VDD3, E8 VDD11, E9 VDD10, E10 VDD15, E11 VCAP2, F2 VSS13-VSS18, F4 VDD13, F5 VDD17, F6 VSS3, F7 VSS11, F8 VSS10, F9 VSS15, F10 VSS2, F11 VDD2, G5 VDD18, G6 VSS17, G10 VSS9, G11 VDD_USB33, H5 VDD5, H6 VSS5, H10 VSS20, H11 VDD20, J5 VDD12, J6 VSS12, J10 VSS8, J11 VDD8, K5 VDD4, K6 VSS4, K7 VSS6, K8 VSS7, K9 VSS1, K10 VSS14, K11 VDD14, L5 BYPASS-REG, L6 VSS19, L7 VDD19, L8 VDD6, L9 VDD7, L10 VDD1, L11 VCAP1, M1 VSSA, N1 VREF-, P1 VREF+, R1 VDDA

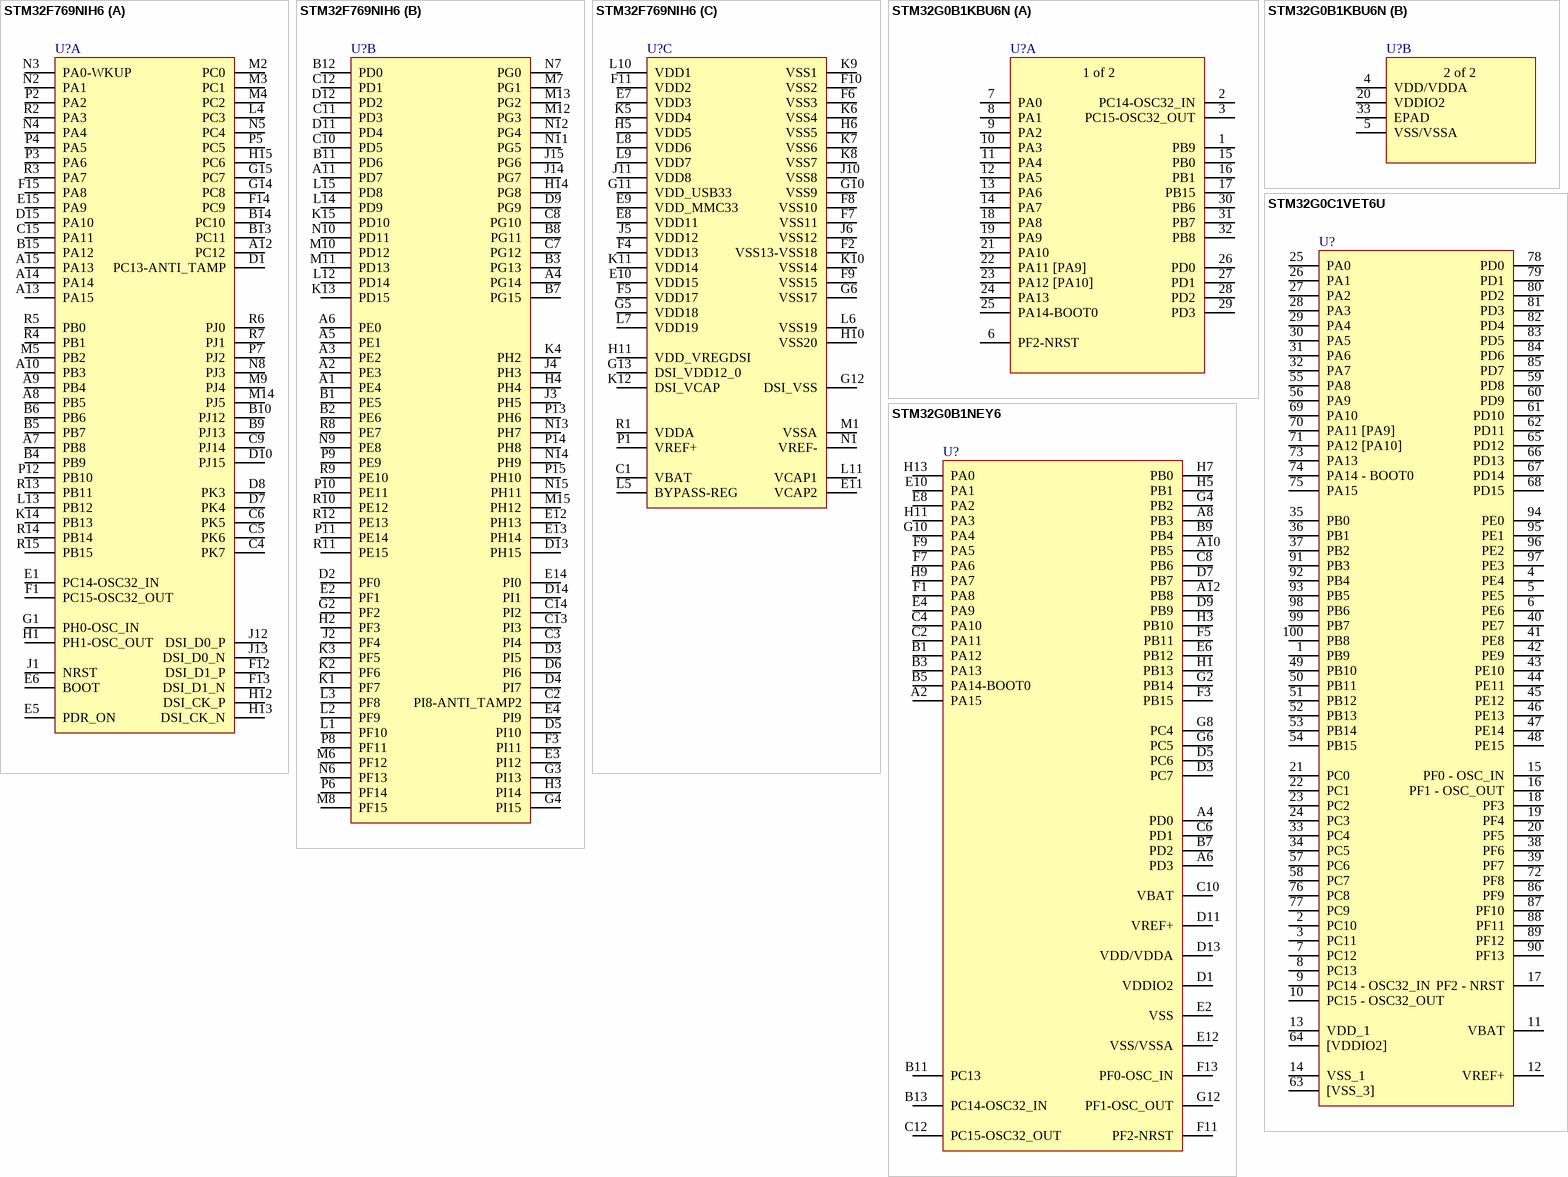
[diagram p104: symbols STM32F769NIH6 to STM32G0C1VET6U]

## STM32F769NIH6
designator U?
part A pins: A7 PB8, A8 PB5, A9 PB4, A10 PB3, A12 PC12, A13 PA15, A14 PA14, A15 PA13, B4 PB9, B5 PB7, B6 PB6, B9 PJ13, B10 PJ12, B13 PC11, B14 PC10, B15 PA12, C4 PK7, C5 PK6, C6 PK5, C9 PJ14, C15 PA11, D1 PC13-ANTI_TAMP, D7 PK4, D8 PK3, D10 PJ15, D15 PA10, E1 PC14-OSC32_IN, E5 PDR_ON, E6 BOOT, E15 PA9, F1 PC15-OSC32_OUT, F12 DSI_D1_P, F13 DSI_D1_N, F14 PC9, F15 PA8, G1 PH0-OSC_IN, G14 PC8, G15 PC7, H1 PH1-OSC_OUT, H12 DSI_CK_P, H13 DSI_CK_N, H15 PC6, J1 NRST, J12 DSI_D0_P, J13 DSI_D0_N, K14 PB13, L4 PC3, L13 PB12, M2 PC0, M3 PC1, M4 PC2, M5 PB2, M9 PJ4, M14 PJ5, N2 PA1, N3 PA0-WKUP, N4 PA4, N5 PC4, N8 PJ3, P2 PA2, P3 PA6, P4 PA5, P5 PC5, P7 PJ2, P12 PB10, R2 PA3, R3 PA7, R4 PB1, R5 PB0, R6 PJ0, R7 PJ1, R13 PB11, R14 PB14, R15 PB15
part B pins: A1 PE4, A2 PE3, A3 PE2, A4 PG14, A5 PE1, A6 PE0, A11 PD7, B1 PE5, B2 PE6, B3 PG13, B7 PG15, B8 PG11, B11 PD6, B12 PD0, C2 PI8-ANTI_TAMP2, C3 PI4, C7 PG12, C8 PG10, C10 PD5, C11 PD3, C12 PD1, C13 PI3, C14 PI2, D2 PF0, D3 PI5, D4 PI7, D5 PI10, D6 PI6, D9 PG9, D11 PD4, D12 PD2, D13 PH15, D14 PI1, E2 PF1, E3 PI12, E4 PI9, E12 PH13, E13 PH14, E14 PI0, F3 PI11, G2 PF2, G3 PI13, G4 PI15, H2 PF3, H3 PI14, H4 PH4, H14 PG8, J2 PF4, J3 PH5, J4 PH3, J14 PG7, J15 PG6, K1 PF7, K2 PF6, K3 PF5, K4 PH2, K13 PD15, K15 PD10, L1 PF10, L2 PF9, L3 PF8, L12 PD14, L14 PD9, L15 PD8, M6 PF12, M7 PG1, M8 PF15, M10 PD12, M11 PD13, M12 PG3, M13 PG2, M15 PH12, N6 PF13, N7 PG0, N9 PE8, N10 PD11, N11 PG5, N12 PG4, N13 PH7, N14 PH9, N15 PH11, P6 PF14, P8 PF11, P9 PE9, P10 PE11, P11 PE14, P13 PH6, P14 PH8, P15 PH10, R8 PE7, R9 PE10, R10 PE12, R11 PE15, R12 PE13
part C pins: C1 VBAT, E7 VDD3, E8 VDD11, E9 VDD_MMC33, E10 VDD15, E11 VCAP2, F2 VSS13-VSS18, F4 VDD13, F5 VDD17, F6 VSS3, F7 VSS11, F8 VSS10, F9 VSS15, F10 VSS2, F11 VDD2, G5 VDD18, G6 VSS17, G10 VSS9, G11 VDD_USB33, G12  DSI_VSS (power), G13 DSI_VDD12_0 (power), H5 VDD5, H6 VSS5, H10 VSS20, H11 VDD_VREGDSI, J5 VDD12, J6 VSS12, J10 VSS8, J11 VDD8, K5 VDD4, K6 VSS4, K7 VSS6, K8 VSS7, K9 VSS1, K10 VSS14, K11 VDD14, K12 DSI_VCAP (power), L5 BYPASS-REG, L6 VSS19, L7 VDD19, L8 VDD6, L9 VDD7, L10 VDD1, L11 VCAP1, M1 VSSA, N1 VREF-, P1 VREF+, R1 VDDA
2 alternate drawings of the same symbol

## STM32G0B1KBU6N
designator U?
part A pins: 1 PB9, 2 PC14-OSC32_IN, 3 PC15-OSC32_OUT, 6 PF2-NRST, 7 PA0, 8 PA1, 9 PA2, 10 PA3, 11 PA4, 12 PA5, 13 PA6, 14 PA7, 15 PB0, 16 PB1, 17 PB15, 18 PA8, 19 PA9, 21 PA10, 22 PA11 [PA9], 23 PA12 [PA10], 24 PA13, 25 PA14-BOOT0, 26 PD0, 27 PD1, 28 PD2, 29 PD3, 30 PB6, 31 PB7, 32 PB8
part B pins: 4 VDD/VDDA, 5 VSS/VSSA, 20 VDDIO2, 33 EPAD

## STM32G0B1NEY6
designator U?
pins: A2 PA15, A4 PD0, A6 PD3, A8 PB3, A10 PB5, A12 PB8, B1 PA12, B3 PA13, B5 PA14-BOOT0, B7 PD2, B9 PB4, B11 PC13, B13 PC14-OSC32_IN, C2 PA11, C4 PA10, C6 PD1, C8 PB6, C10 VBAT, C12 PC15-OSC32_OUT, D1 VDDIO2, D3 PC7, D5 PC6, D7 PB7, D9 PB9, D11 VREF+, D13 VDD/VDDA, E2 VSS, E4 PA9, E6 PB12, E8 PA2, E10 PA1, E12 VSS/VSSA, F1 PA8, F3 PB15, F5 PB11, F7 PA6, F9 PA5, F11 PF2-NRST, F13 PF0-OSC_IN, G2 PB14, G4 PB2, G6 PC5, G8 PC4, G10 PA4, G12 PF1-OSC_OUT, H1 PB13, H3 PB10, H5 PB1, H7 PB0, H9 PA7, H11 PA3, H13 PA0

## STM32G0C1VET6U
designator U?
pins: 1 PB9, 2 PC10, 3 PC11, 4 PE4, 5 PE5, 6 PE6, 7 PC12, 8 PC13, 9 PC14 - OSC32_IN, 10 PC15 - OSC32_OUT, 11 VBAT, 12 VREF+, 13 VDD_1, 14 VSS_1, 15 PF0 - OSC_IN, 16 PF1 - OSC_OUT, 17 PF2 - NRST, 18 PF3, 19 PF4, 20 PF5, 21 PC0, 22 PC1, 23 PC2, 24 PC3, 25 PA0, 26 PA1, 27 PA2, 28 PA3, 29 PA4, 30 PA5, 31 PA6, 32 PA7, 33 PC4, 34 PC5, 35 PB0, 36 PB1, 37 PB2, 38 PF6, 39 PF7, 40 PE7, 41 PE8, 42 PE9, 43 PE10, 44 PE11, 45 PE12, 46 PE13, 47 PE14, 48 PE15, 49 PB10, 50 PB11, 51 PB12, 52 PB13, 53 PB14, 54 PB15, 55 PA8, 56 PA9, 57 PC6, 58 PC7, 59 PD8, 60 PD9, 61 PD10, 62 PD11, 63 [VSS_3], 64 [VDDIO2], 65 PD12, 66 PD13, 67 PD14, 68 PD15, 69 PA10, 70 PA11 [PA9], 71 PA12 [PA10], 72 PF8, 73 PA13, 74 PA14 - BOOT0, 75 PA15, 76 PC8, 77 PC9, 78 PD0, 79 PD1, 80 PD2, 81 PD3, 82 PD4, 83 PD5, 84 PD6, 85 PD7, 86 PF9, 87 PF10, 88 PF11, 89 PF12, 90 PF13, 91 PB3, 92 PB4, 93 PB5, 94 PE0, 95 PE1, 96 PE2, 97 PE3, 98 PB6, 99 PB7, 100 PB8

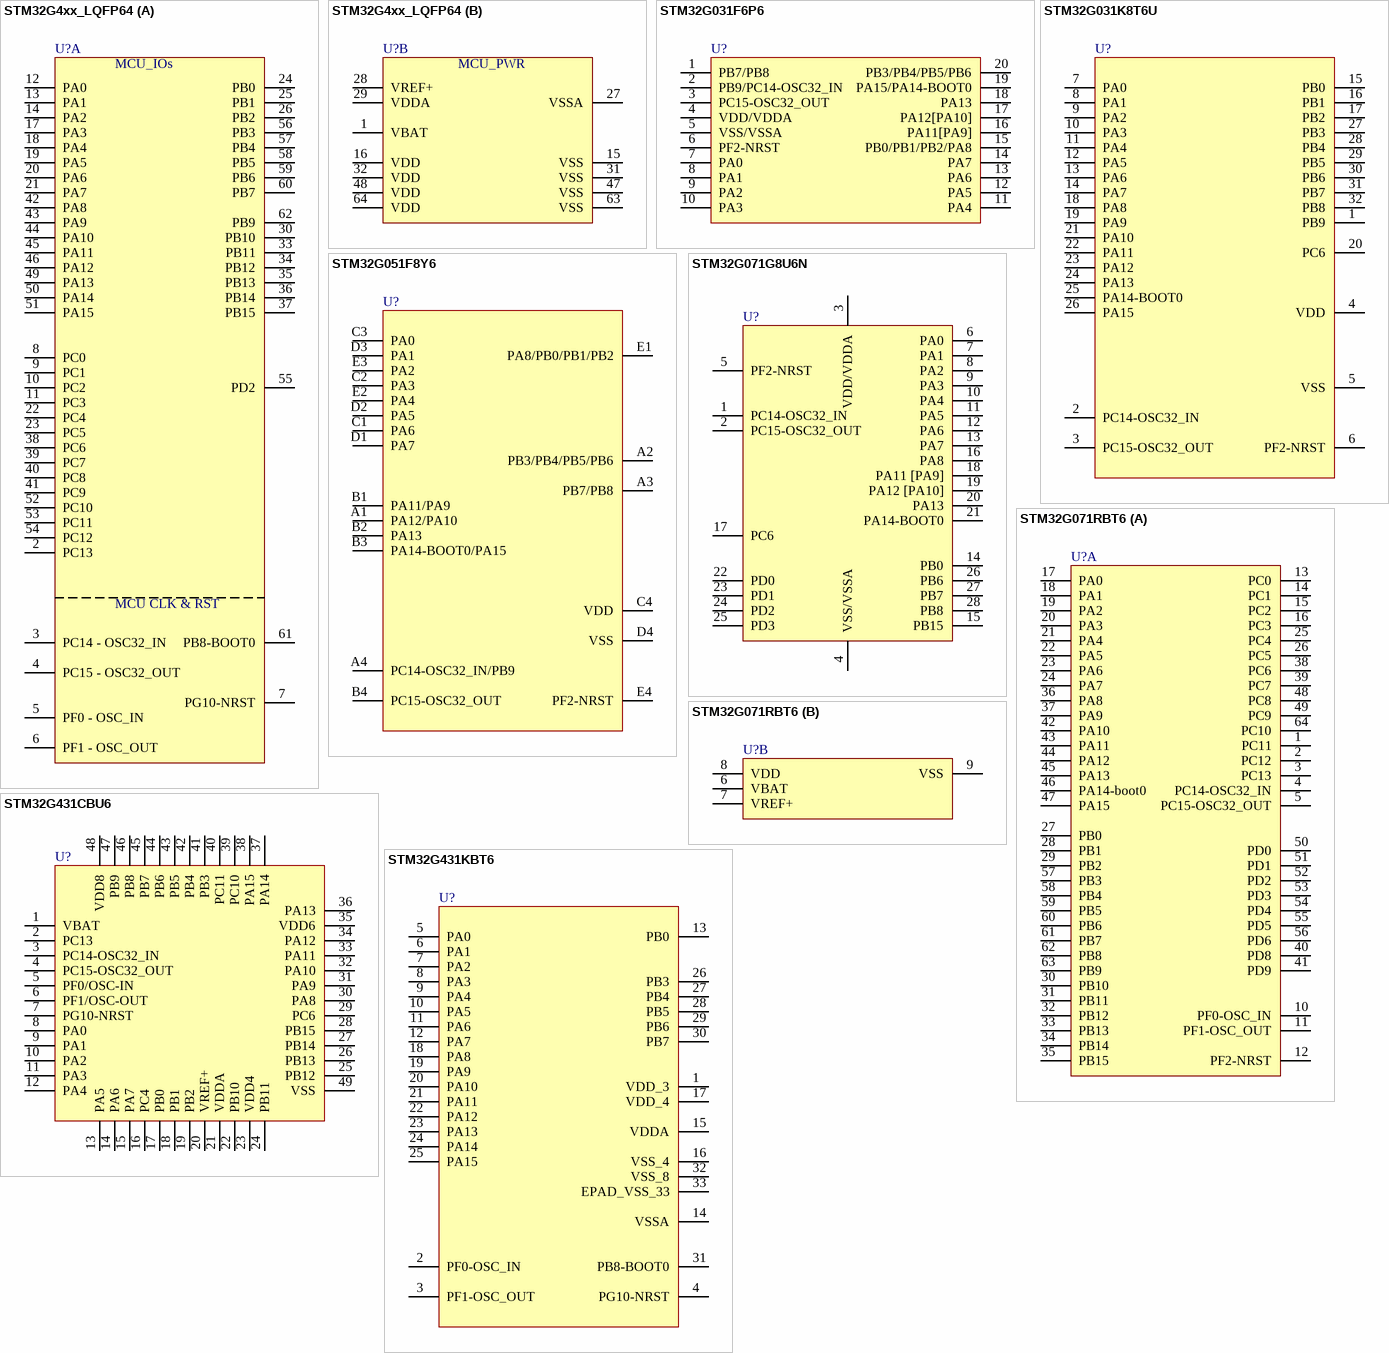
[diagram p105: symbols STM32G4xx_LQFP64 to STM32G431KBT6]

## STM32G4xx_LQFP64
designator U?
part A pins: 2 PC13, 3 PC14 - OSC32_IN, 4 PC15 - OSC32_OUT, 5 PF0 - OSC_IN, 6 PF1 - OSC_OUT, 7 PG10-NRST, 8 PC0, 9 PC1, 10 PC2, 11 PC3, 12 PA0, 13 PA1, 14 PA2, 17 PA3, 18 PA4, 19 PA5, 20 PA6, 21 PA7, 22 PC4, 23 PC5, 24 PB0, 25 PB1, 26 PB2, 30 PB10, 33 PB11, 34 PB12, 35 PB13, 36 PB14, 37 PB15, 38 PC6, 39 PC7, 40 PC8, 41 PC9, 42 PA8, 43 PA9, 44 PA10, 45 PA11, 46 PA12, 49 PA13, 50 PA14, 51 PA15, 52 PC10, 53 PC11, 54 PC12, 55 PD2, 56 PB3, 57 PB4, 58 PB5, 59 PB6, 60 PB7, 61 PB8-BOOT0, 62 PB9
part B pins: 1 VBAT, 15 VSS, 16 VDD, 27 VSSA, 28 VREF+, 29 VDDA, 31 VSS, 32 VDD, 47 VSS, 48 VDD, 63 VSS, 64 VDD

## STM32G031F6P6
designator U?
pins: 1 PB7/PB8, 2 PB9/PC14-OSC32_IN, 3 PC15-OSC32_OUT, 4 VDD/VDDA, 5 VSS/VSSA, 6 PF2-NRST, 7 PA0, 8 PA1, 9 PA2, 10 PA3, 11 PA4, 12 PA5, 13 PA6, 14 PA7, 15 PB0/PB1/PB2/PA8, 16 PA11[PA9], 17 PA12[PA10], 18 PA13, 19 PA15/PA14-BOOT0, 20 PB3/PB4/PB5/PB6

## STM32G031K8T6U
designator U?
pins: 1 PB9, 2 PC14-OSC32_IN, 3 PC15-OSC32_OUT, 4 VDD, 5 VSS, 6 PF2-NRST, 7 PA0, 8 PA1, 9 PA2, 10 PA3, 11 PA4, 12 PA5, 13 PA6, 14 PA7, 15 PB0, 16 PB1, 17 PB2, 18 PA8, 19 PA9, 20 PC6, 21 PA10, 22 PA11, 23 PA12, 24 PA13, 25 PA14-BOOT0, 26 PA15, 27 PB3, 28 PB4, 29 PB5, 30 PB6, 31 PB7, 32 PB8

## STM32G051F8Y6
designator U?
pins: A1 PA12/PA10, A2 PB3/PB4/PB5/PB6, A3 PB7/PB8, A4 PC14-OSC32_IN/PB9, B1 PA11/PA9, B2 PA13, B3 PA14-BOOT0/PA15, B4 PC15-OSC32_OUT, C1 PA6, C2 PA3, C3 PA0, C4 VDD, D1 PA7, D2 PA5, D3 PA1, D4 VSS, E1 PA8/PB0/PB1/PB2, E2 PA4, E3 PA2, E4 PF2-NRST

## STM32G071G8U6N
designator U?
pins: 1 PC14-OSC32_IN, 2 PC15-OSC32_OUT, 3 VDD/VDDA, 4 VSS/VSSA, 5 PF2-NRST, 6 PA0, 7 PA1, 8 PA2, 9 PA3, 10 PA4, 11 PA5, 12 PA6, 13 PA7, 14 PB0, 15 PB15, 16 PA8, 17 PC6, 18 PA11 [PA9], 19 PA12 [PA10], 20 PA13, 21 PA14-BOOT0, 22 PD0, 23 PD1, 24 PD2, 25 PD3, 26 PB6, 27 PB7, 28 PB8

## STM32G071RBT6
designator U?
part A pins: 1 PC11, 2 PC12, 3 PC13, 4 PC14-OSC32_IN, 5 PC15-OSC32_OUT, 10 PF0-OSC_IN, 11 PF1-OSC_OUT, 12 PF2-NRST, 13 PC0, 14 PC1, 15 PC2, 16 PC3, 17 PA0, 18 PA1, 19 PA2, 20 PA3, 21 PA4, 22 PA5, 23 PA6, 24 PA7, 25 PC4, 26 PC5, 27 PB0, 28 PB1, 29 PB2, 30 PB10, 31 PB11, 32 PB12, 33 PB13, 34 PB14, 35 PB15, 36 PA8, 37 PA9, 38 PC6, 39 PC7, 40 PD8, 41 PD9, 42 PA10, 43 PA11, 44 PA12, 45 PA13, 46 PA14-boot0, 47 PA15, 48 PC8, 49 PC9, 50 PD0, 51 PD1, 52 PD2, 53 PD3, 54 PD4, 55 PD5, 56 PD6, 57 PB3, 58 PB4, 59 PB5, 60 PB6, 61 PB7, 62 PB8, 63 PB9, 64 PC10
part B pins: 6 VBAT (power), 7 VREF+ (power), 8 VDD (power), 9 VSS

## STM32G431CBU6
designator U?
pins: 1 VBAT, 2 PC13, 3 PC14-OSC32_IN, 4 PC15-OSC32_OUT, 5 PF0/OSC-IN, 6 PF1/OSC-OUT, 7 PG10-NRST, 8 PA0, 9 PA1, 10 PA2, 11 PA3, 12 PA4, 13 PA5, 14 PA6, 15 PA7, 16 PC4, 17 PB0, 18 PB1, 19 PB2, 20 VREF+, 21 VDDA, 22 PB10, 23 VDD4, 24 PB11, 25 PB12, 26 PB13, 27 PB14, 28 PB15, 29 PC6, 30 PA8, 31 PA9, 32 PA10, 33 PA11, 34 PA12, 35 VDD6, 36 PA13, 37 PA14, 38 PA15, 39 PC10, 40 PC11, 41 PB3, 42 PB4, 43 PB5, 44 PB6, 45 PB7, 46 PB8, 47 PB9, 48 VDD8, 49 VSS

## STM32G431KBT6
designator U?
pins: 1 VDD_3, 2 PF0-OSC_IN, 3 PF1-OSC_OUT, 4 PG10-NRST, 5 PA0, 6 PA1, 7 PA2, 8 PA3, 9 PA4, 10 PA5, 11 PA6, 12 PA7, 13 PB0, 14 VSSA, 15 VDDA, 16 VSS_4, 17 VDD_4, 18 PA8, 19 PA9, 20 PA10, 21 PA11, 22 PA12, 23 PA13, 24 PA14, 25 PA15, 26 PB3, 27 PB4, 28 PB5, 29 PB6, 30 PB7, 31 PB8-BOOT0, 32 VSS_8, 33 EPAD_VSS_33

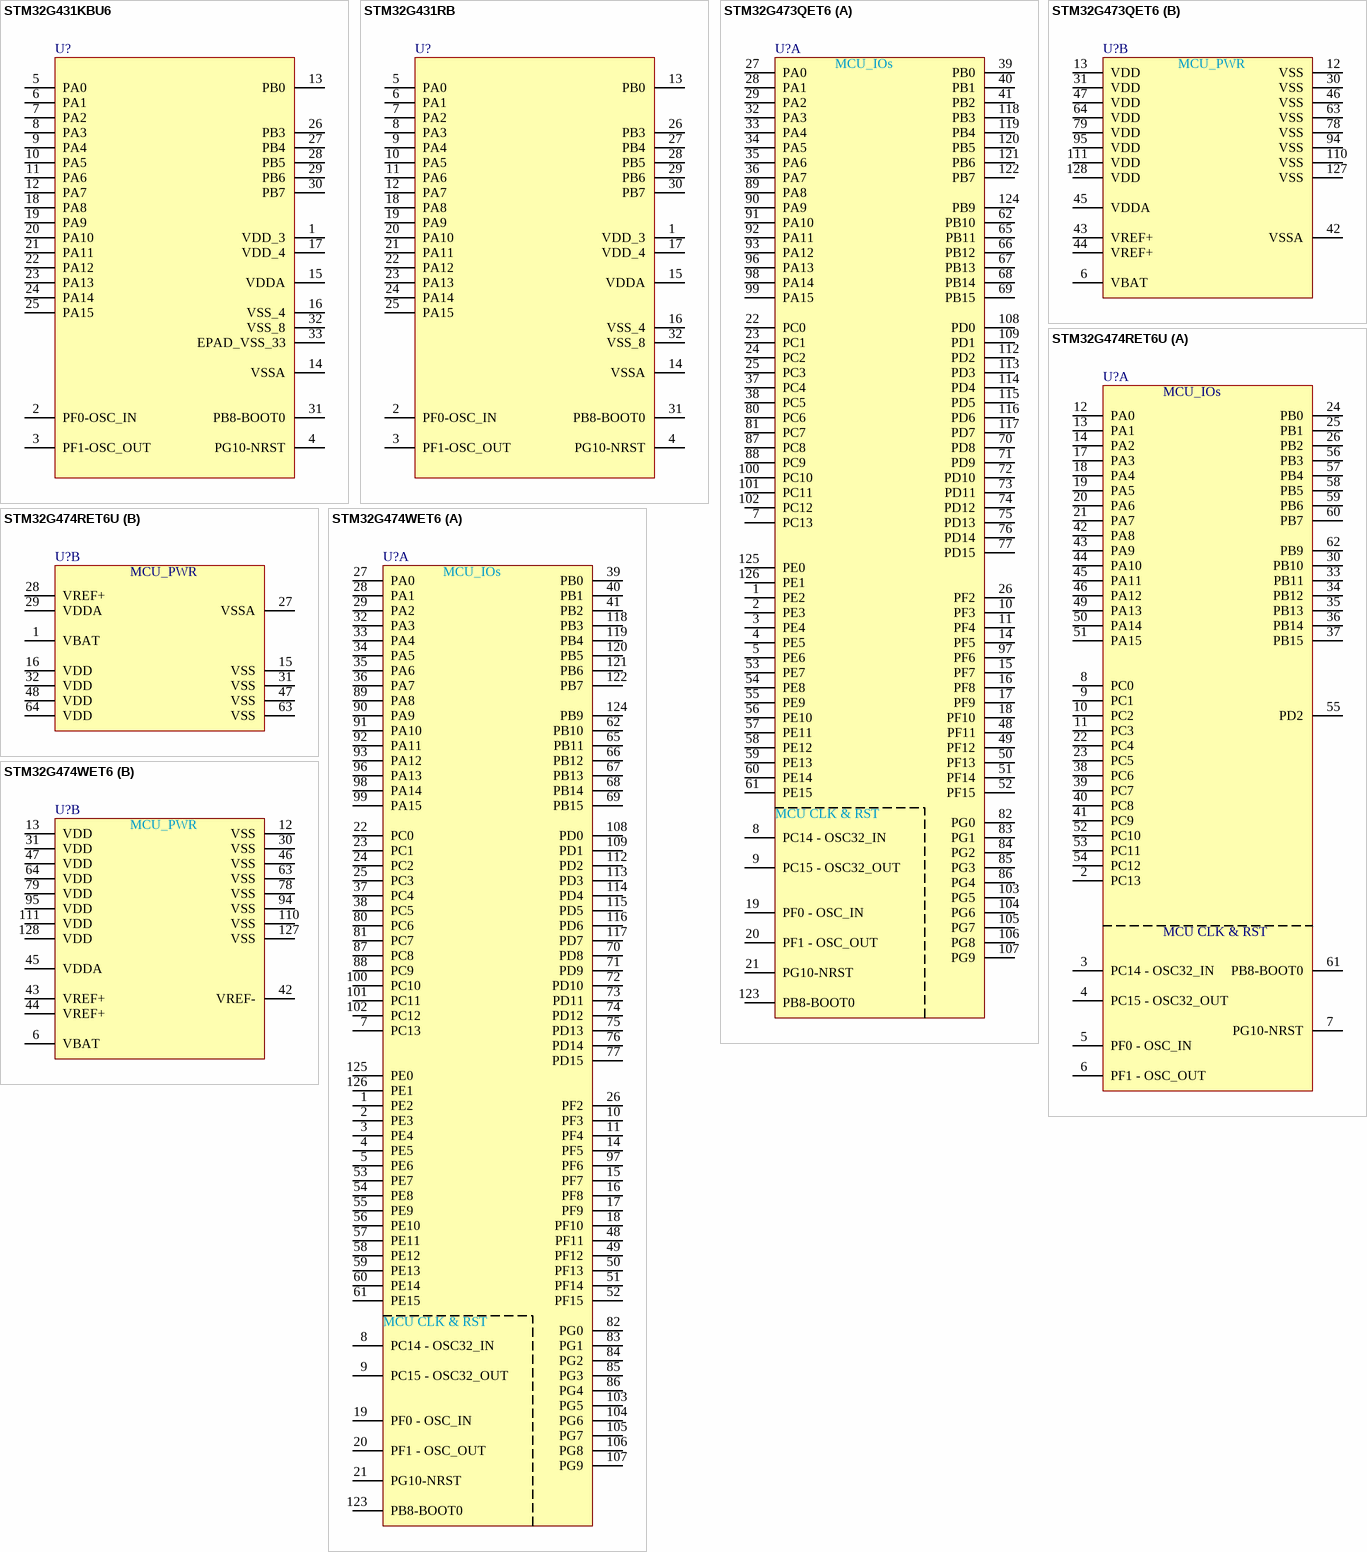
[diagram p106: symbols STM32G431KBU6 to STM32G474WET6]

## STM32G431KBU6
designator U?
pins: 1 VDD_3, 2 PF0-OSC_IN, 3 PF1-OSC_OUT, 4 PG10-NRST, 5 PA0, 6 PA1, 7 PA2, 8 PA3, 9 PA4, 10 PA5, 11 PA6, 12 PA7, 13 PB0, 14 VSSA, 15 VDDA, 16 VSS_4, 17 VDD_4, 18 PA8, 19 PA9, 20 PA10, 21 PA11, 22 PA12, 23 PA13, 24 PA14, 25 PA15, 26 PB3, 27 PB4, 28 PB5, 29 PB6, 30 PB7, 31 PB8-BOOT0, 32 VSS_8, 33 EPAD_VSS_33

## STM32G431RB
designator U?
pins: 1 VDD_3, 2 PF0-OSC_IN, 3 PF1-OSC_OUT, 4 PG10-NRST, 5 PA0, 6 PA1, 7 PA2, 8 PA3, 9 PA4, 10 PA5, 11 PA6, 12 PA7, 13 PB0, 14 VSSA, 15 VDDA, 16 VSS_4, 17 VDD_4, 18 PA8, 19 PA9, 20 PA10, 21 PA11, 22 PA12, 23 PA13, 24 PA14, 25 PA15, 26 PB3, 27 PB4, 28 PB5, 29 PB6, 30 PB7, 31 PB8-BOOT0, 32 VSS_8

## STM32G473QET6
designator U?
part A pins: 1 PE2, 2 PE3, 3 PE4, 4 PE5, 5 PE6, 7 PC13, 8 PC14 - OSC32_IN, 9 PC15 - OSC32_OUT, 10 PF3, 11 PF4, 14 PF5, 15 PF7, 16 PF8, 17 PF9, 18 PF10, 19 PF0 - OSC_IN, 20 PF1 - OSC_OUT, 21 PG10-NRST, 22 PC0, 23 PC1, 24 PC2, 25 PC3, 26 PF2, 27 PA0, 28 PA1, 29 PA2, 32 PA3, 33 PA4, 34 PA5, 35 PA6, 36 PA7, 37 PC4, 38 PC5, 39 PB0, 40 PB1, 41 PB2, 48 PF11, 49 PF12, 50 PF13, 51 PF14, 52 PF15, 53 PE7, 54 PE8, 55 PE9, 56 PE10, 57 PE11, 58 PE12, 59 PE13, 60 PE14, 61 PE15, 62 PB10, 65 PB11, 66 PB12, 67 PB13, 68 PB14, 69 PB15, 70 PD8, 71 PD9, 72 PD10, 73 PD11, 74 PD12, 75 PD13, 76 PD14, 77 PD15, 80 PC6, 81 PC7, 82 PG0, 83 PG1, 84 PG2, 85 PG3, 86 PG4, 87 PC8, 88 PC9, 89 PA8, 90 PA9, 91 PA10, 92 PA11, 93 PA12, 96 PA13, 97 PF6, 98 PA14, 99 PA15, 100 PC10, 101 PC11, 102 PC12, 103 PG5, 104 PG6, 105 PG7, 106 PG8, 107 PG9, 108 PD0, 109 PD1, 112 PD2, 113 PD3, 114 PD4, 115 PD5, 116 PD6, 117 PD7, 118 PB3, 119 PB4, 120 PB5, 121 PB6, 122 PB7, 123 PB8-BOOT0, 124 PB9, 125 PE0, 126 PE1
part B pins: 6 VBAT, 12 VSS, 13 VDD, 30 VSS, 31 VDD, 42 VSSA, 43 VREF+, 44 VREF+, 45 VDDA, 46 VSS, 47 VDD, 63 VSS, 64 VDD, 78 VSS, 79 VDD, 94 VSS, 95 VDD, 110 VSS, 111 VDD, 127 VSS, 128 VDD

## STM32G474RET6U
designator U?
part A pins: 2 PC13, 3 PC14 - OSC32_IN, 4 PC15 - OSC32_OUT, 5 PF0 - OSC_IN, 6 PF1 - OSC_OUT, 7 PG10-NRST, 8 PC0, 9 PC1, 10 PC2, 11 PC3, 12 PA0, 13 PA1, 14 PA2, 17 PA3, 18 PA4, 19 PA5, 20 PA6, 21 PA7, 22 PC4, 23 PC5, 24 PB0, 25 PB1, 26 PB2, 30 PB10, 33 PB11, 34 PB12, 35 PB13, 36 PB14, 37 PB15, 38 PC6, 39 PC7, 40 PC8, 41 PC9, 42 PA8, 43 PA9, 44 PA10, 45 PA11, 46 PA12, 49 PA13, 50 PA14, 51 PA15, 52 PC10, 53 PC11, 54 PC12, 55 PD2, 56 PB3, 57 PB4, 58 PB5, 59 PB6, 60 PB7, 61 PB8-BOOT0, 62 PB9
part B pins: 1 VBAT, 15 VSS, 16 VDD, 27 VSSA, 28 VREF+, 29 VDDA, 31 VSS, 32 VDD, 47 VSS, 48 VDD, 63 VSS, 64 VDD

## STM32G474WET6
designator U?
part A pins: 1 PE2, 2 PE3, 3 PE4, 4 PE5, 5 PE6, 7 PC13, 8 PC14 - OSC32_IN, 9 PC15 - OSC32_OUT, 10 PF3, 11 PF4, 14 PF5, 15 PF7, 16 PF8, 17 PF9, 18 PF10, 19 PF0 - OSC_IN, 20 PF1 - OSC_OUT, 21 PG10-NRST, 22 PC0, 23 PC1, 24 PC2, 25 PC3, 26 PF2, 27 PA0, 28 PA1, 29 PA2, 32 PA3, 33 PA4, 34 PA5, 35 PA6, 36 PA7, 37 PC4, 38 PC5, 39 PB0, 40 PB1, 41 PB2, 48 PF11, 49 PF12, 50 PF13, 51 PF14, 52 PF15, 53 PE7, 54 PE8, 55 PE9, 56 PE10, 57 PE11, 58 PE12, 59 PE13, 60 PE14, 61 PE15, 62 PB10, 65 PB11, 66 PB12, 67 PB13, 68 PB14, 69 PB15, 70 PD8, 71 PD9, 72 PD10, 73 PD11, 74 PD12, 75 PD13, 76 PD14, 77 PD15, 80 PC6, 81 PC7, 82 PG0, 83 PG1, 84 PG2, 85 PG3, 86 PG4, 87 PC8, 88 PC9, 89 PA8, 90 PA9, 91 PA10, 92 PA11, 93 PA12, 96 PA13, 97 PF6, 98 PA14, 99 PA15, 100 PC10, 101 PC11, 102 PC12, 103 PG5, 104 PG6, 105 PG7, 106 PG8, 107 PG9, 108 PD0, 109 PD1, 112 PD2, 113 PD3, 114 PD4, 115 PD5, 116 PD6, 117 PD7, 118 PB3, 119 PB4, 120 PB5, 121 PB6, 122 PB7, 123 PB8-BOOT0, 124 PB9, 125 PE0, 126 PE1
part B pins: 6 VBAT, 12 VSS, 13 VDD, 30 VSS, 31 VDD, 42 VREF-, 43 VREF+, 44 VREF+, 45 VDDA, 46 VSS, 47 VDD, 63 VSS, 64 VDD, 78 VSS, 79 VDD, 94 VSS, 95 VDD, 110 VSS, 111 VDD, 127 VSS, 128 VDD

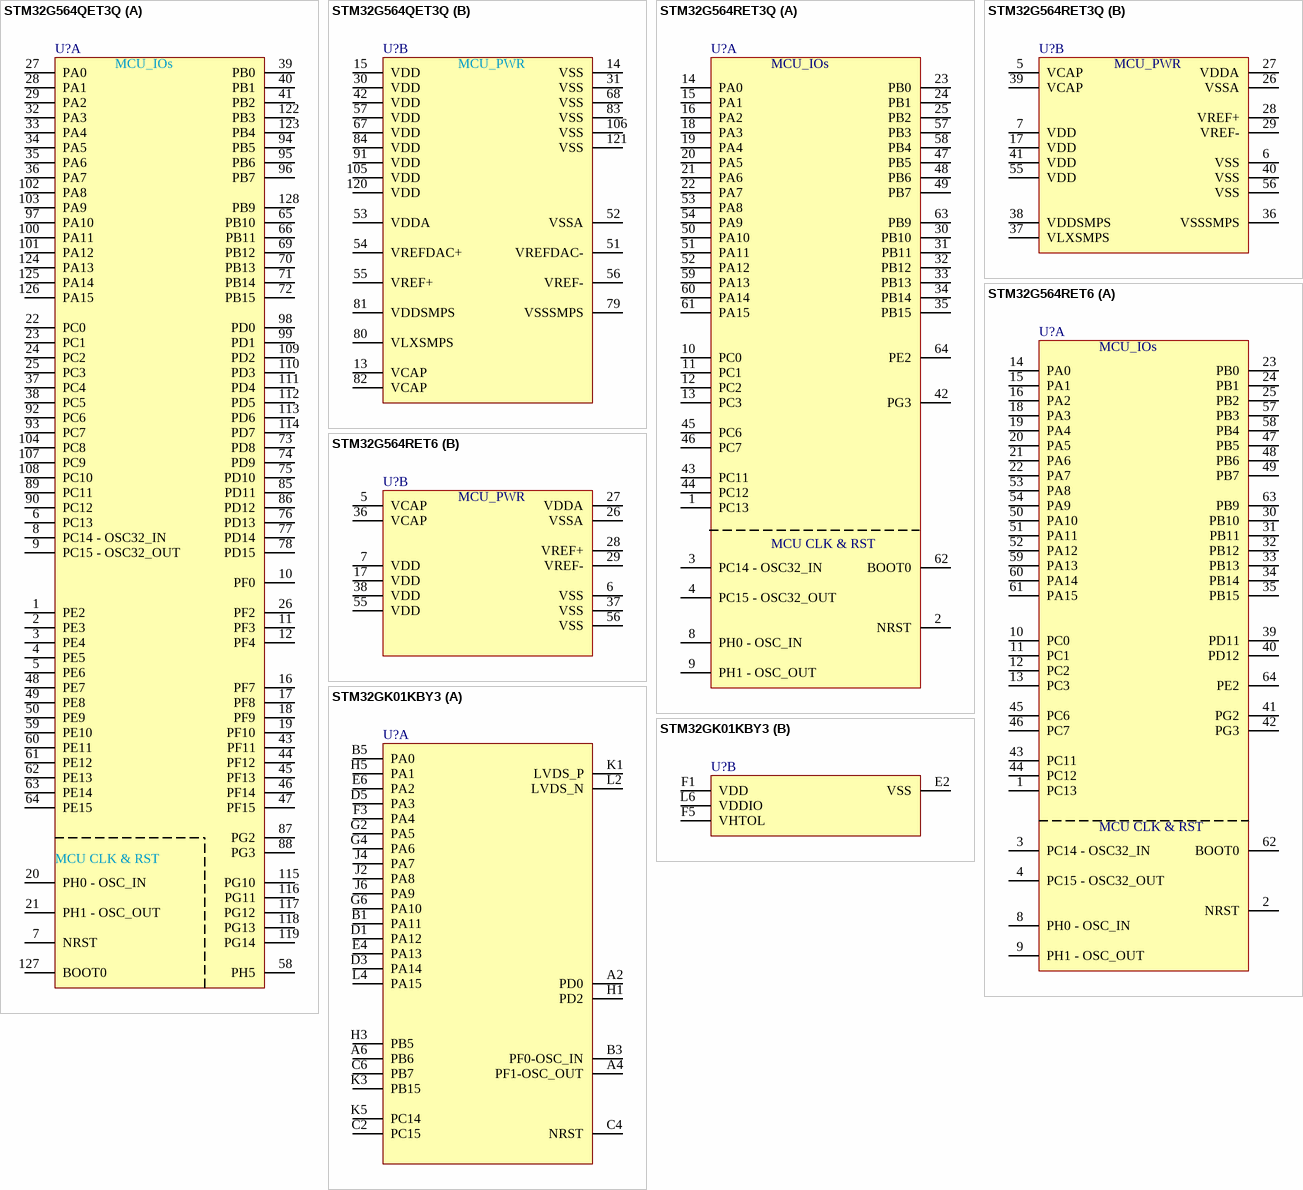
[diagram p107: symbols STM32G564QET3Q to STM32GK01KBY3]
